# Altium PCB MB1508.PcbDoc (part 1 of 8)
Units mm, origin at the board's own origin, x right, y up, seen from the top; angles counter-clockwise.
Board outline 129 x 77 mm, 4 copper layers (Top Layer, GND, POWER, Bottom Layer), stack 1.582 mm thick; 399 components, 297 nets, 1407 pads, 1316 vias.
Unrouted connection lines stored in the file: 535.
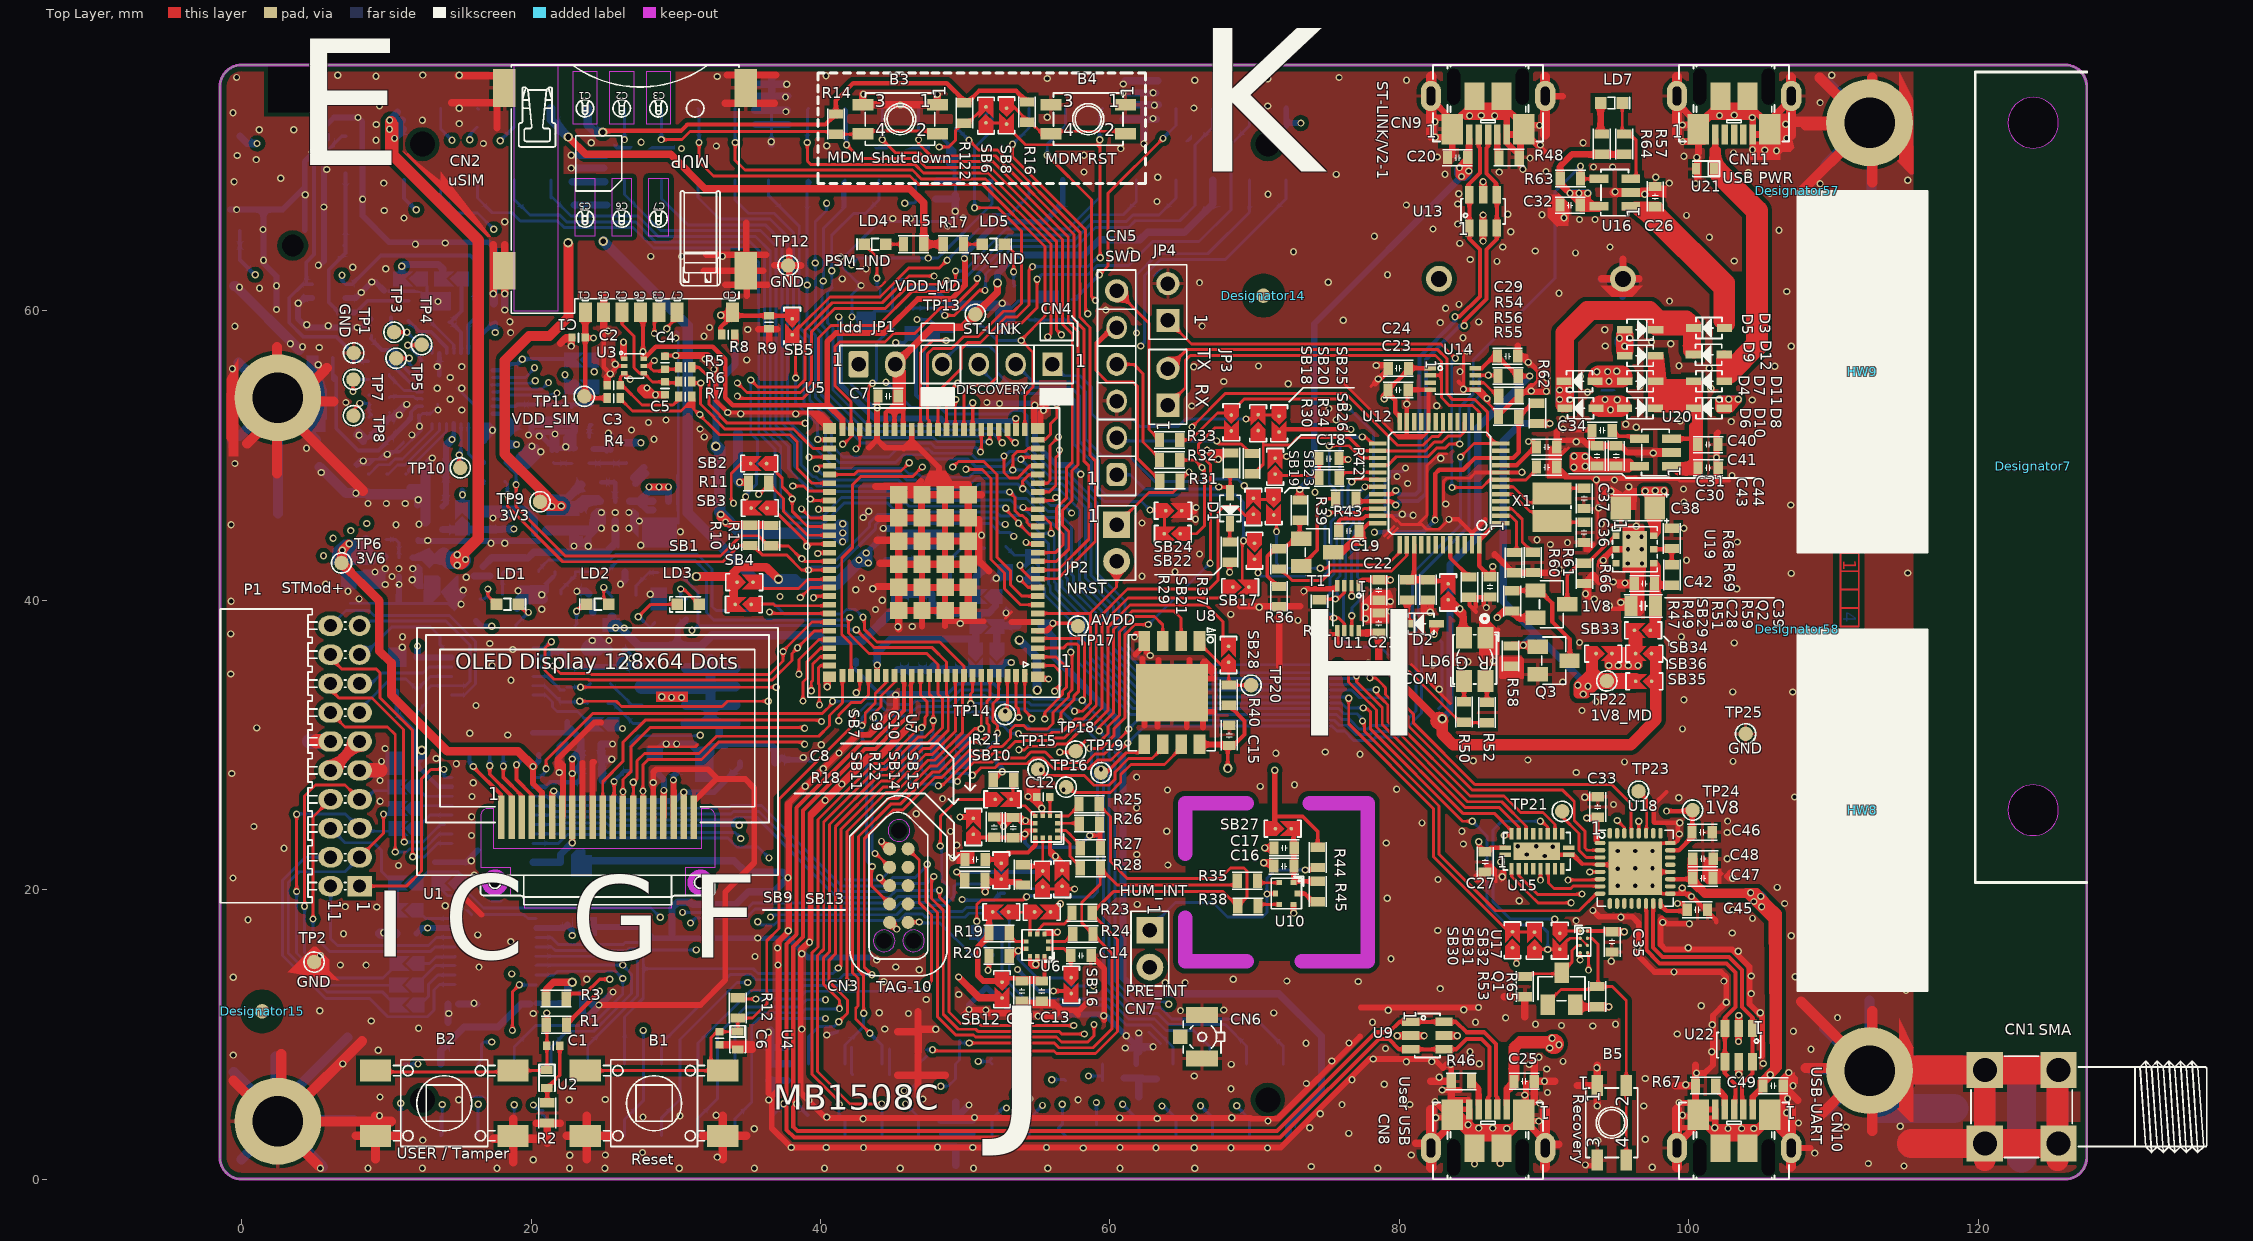
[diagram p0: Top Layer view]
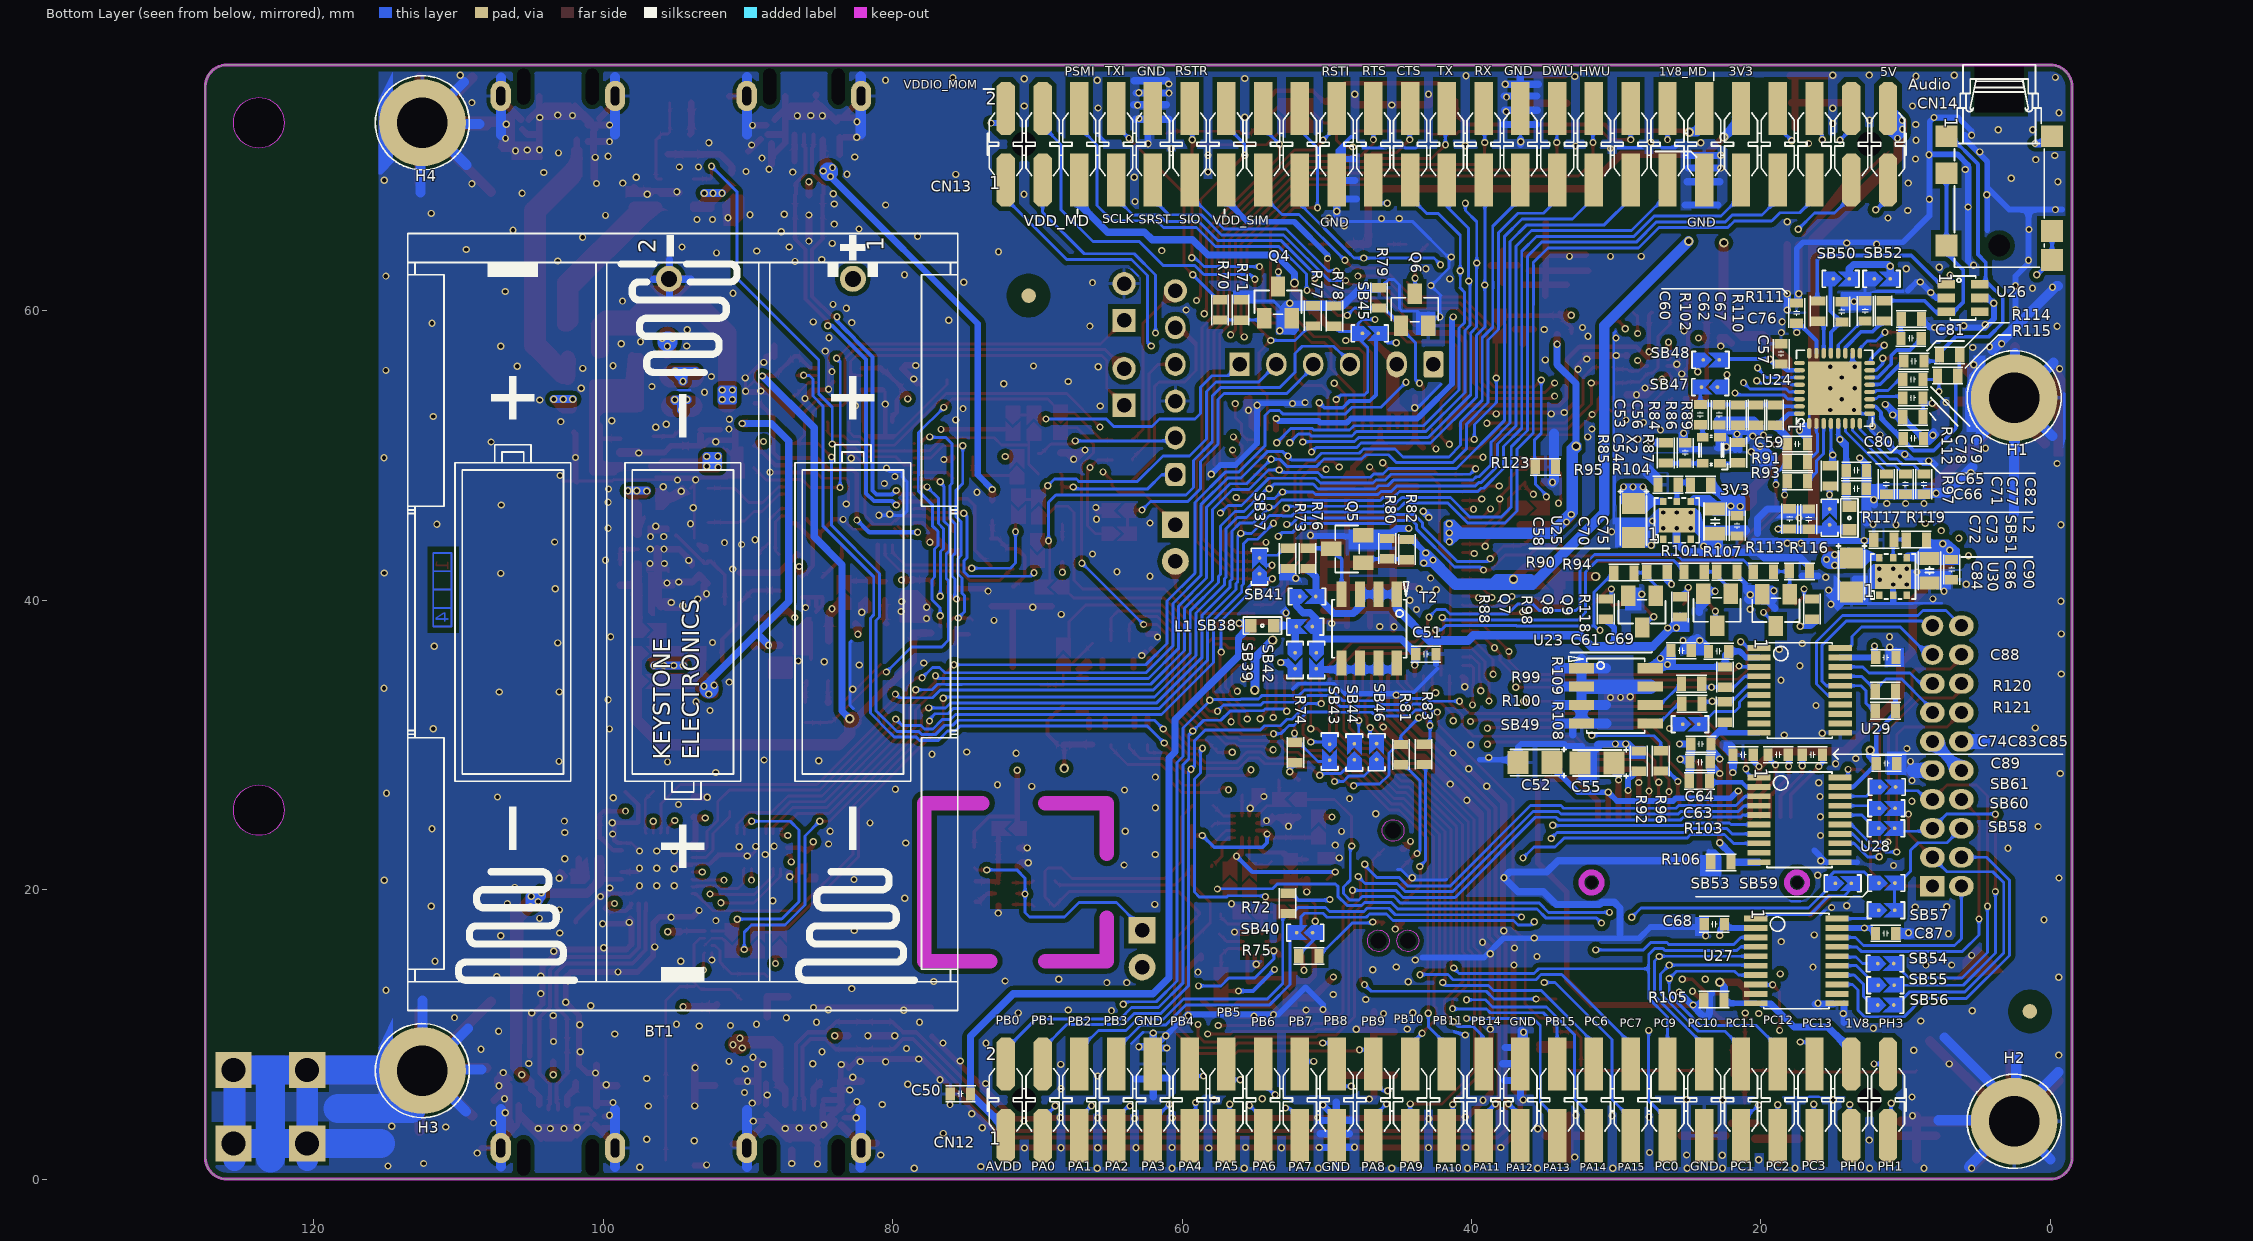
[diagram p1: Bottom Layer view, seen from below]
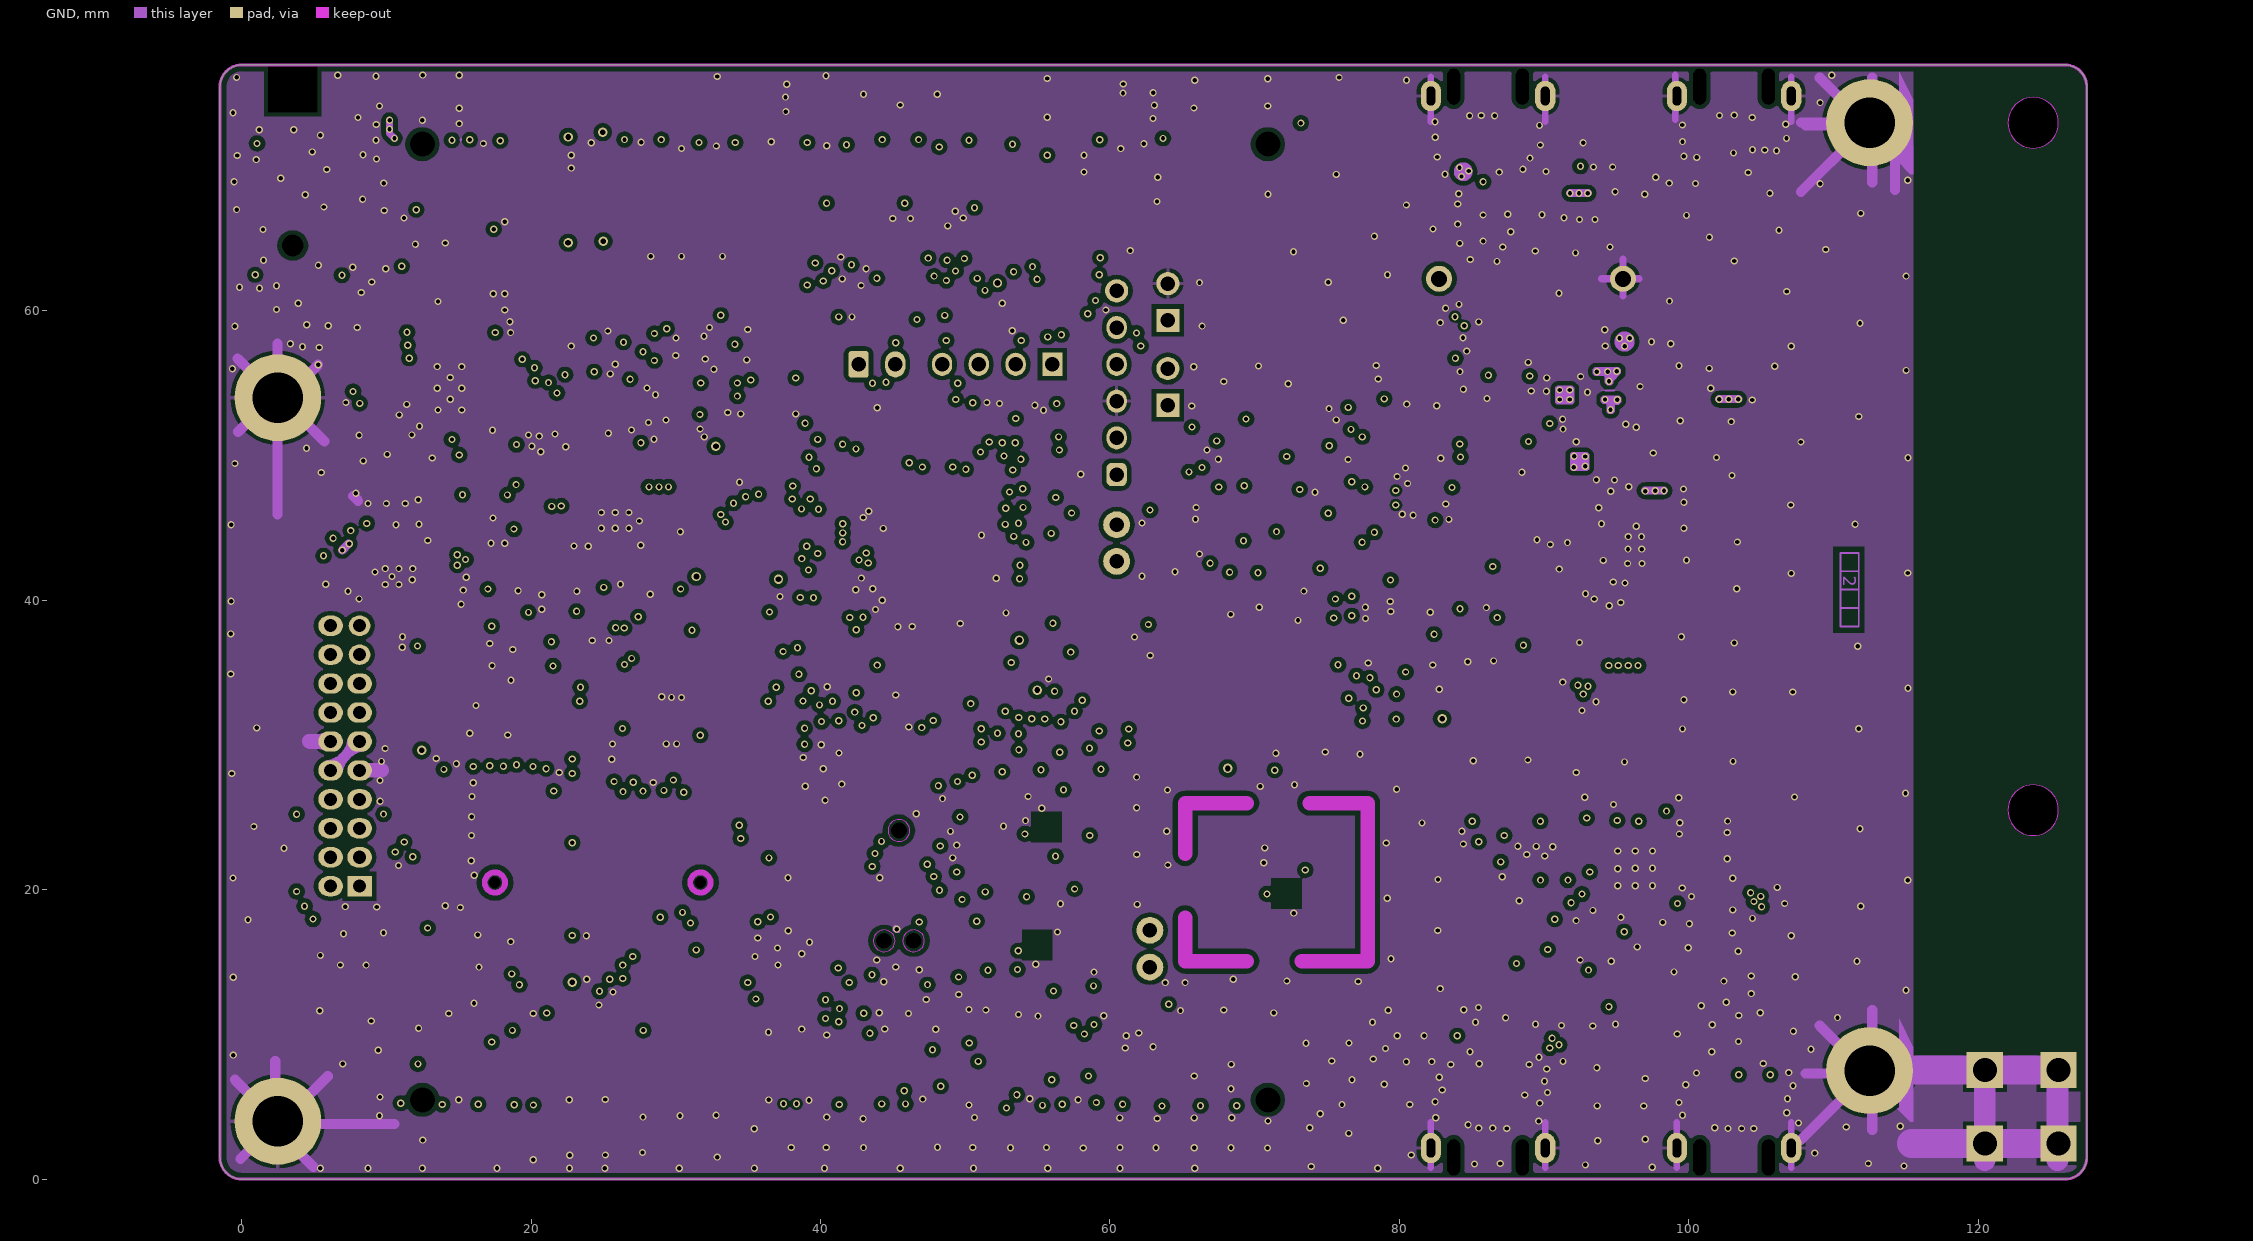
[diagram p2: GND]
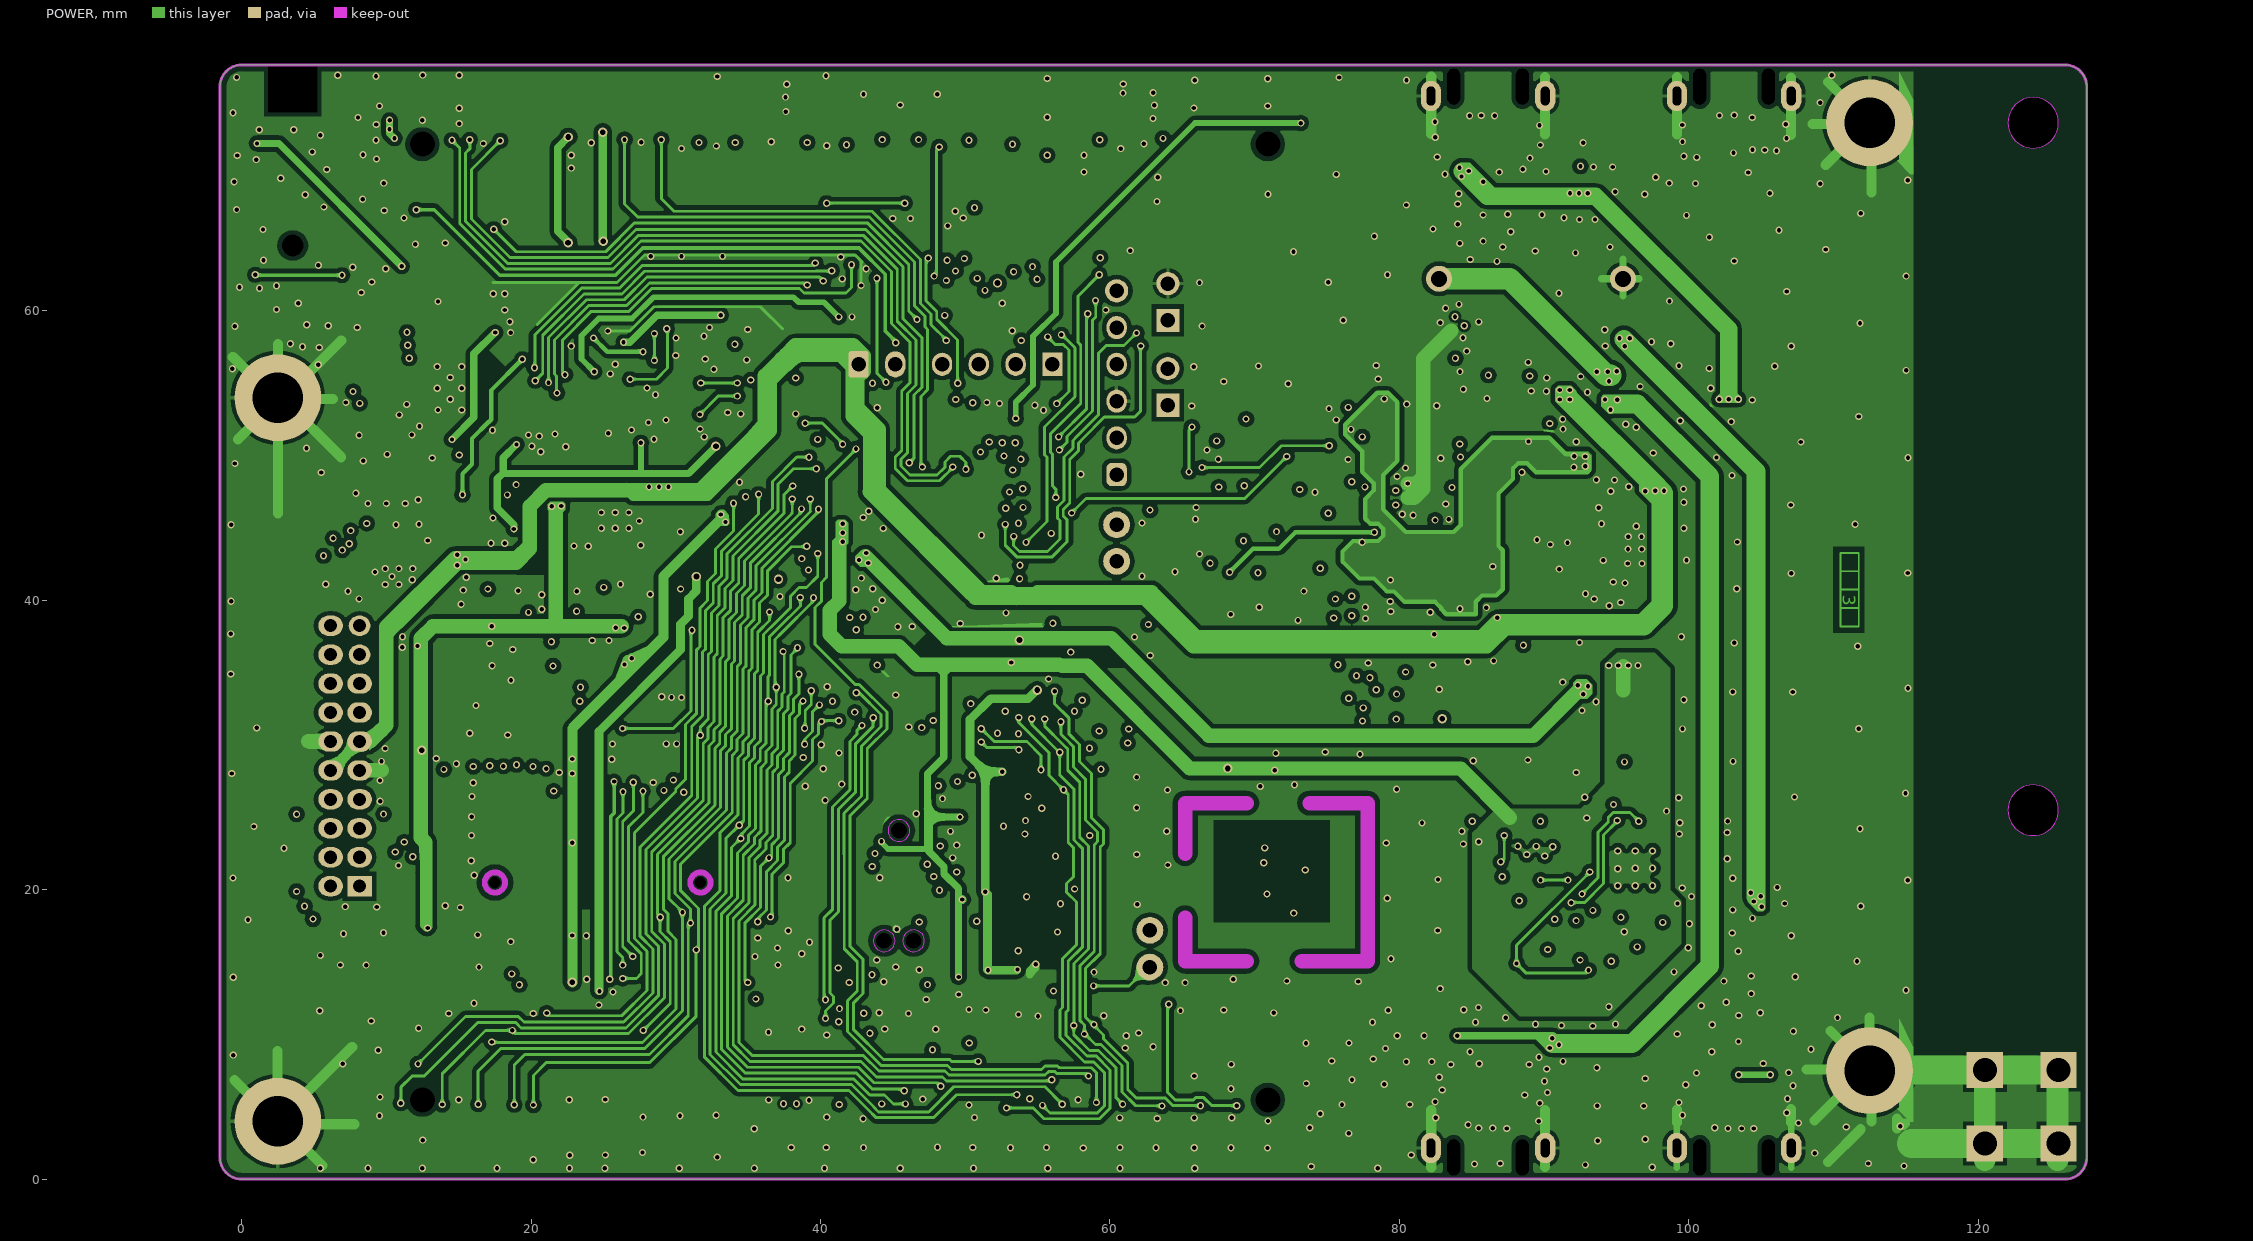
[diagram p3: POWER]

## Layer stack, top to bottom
Top Solder: solder mask 0.0102, Solder Resist, Dk 3.8
Top Layer: signal copper 0.0305
Dielectric 1: core 0.2159, FR-4, Dk 4.2
GND: signal copper 0.0305
Dielectric 2: prepreg 1.0287, Dk 4.4
POWER: signal copper 0.0305
Dielectric 3: core 0.2159, Dk 4.2
Bottom Layer: signal copper 0.0305
Bottom Solder: solder mask 0.0102, Solder Resist, Dk 3.8

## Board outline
-1.5,1.5 ccw(c0,1.5) 0,0 126,0 ccw(c126,1.5) 127.5,1.5 127.5,75.5 ccw(c126,75.5) 126,77 0,77 ccw(c0,75.5) -1.5,75.5
cut-out: 122.05,25.5 ccw(c123.8,25.5) 123.8,23.75 ccw(c123.8,25.5) 125.55,25.5 ccw(c123.8,25.5) 123.8,27.25 ccw(c123.8,25.5)
cut-out: 122.05,73 ccw(c123.8,73) 123.8,71.25 ccw(c123.8,73) 125.55,73 ccw(c123.8,73) 123.8,74.75 ccw(c123.8,73)

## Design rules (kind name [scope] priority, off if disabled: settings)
Clearance KEEP [IsKeepOut] p1: gap=0.35 ignorepadtopadclearanceinfootprint=FALSE
Clearance diff [InAnyDifferentialPair] p2: gap=0.178 ignorepadtopadclearanceinfootprint=FALSE
Clearance via [IsVia vs IsVia] p3: gap=0.4 ignorepadtopadclearanceinfootprint=FALSE
Clearance Polygon [InPolygon] p4: gap=0.3 ignorepadtopadclearanceinfootprint=FALSE
Clearance [All] p5: gap=0.2 ignorepadtopadclearanceinfootprint=FALSE
DiffPairsRouting [All] p1: maxlimit=0.254 minlimit=0.178 mostfreqgap=0.178 toplayer_minwidth=0.279 toplayer_maxwidth=0.279 toplayer_prefwidth=0.279 midlayer1_minwidth=0.279 midlayer1_maxwidth=0.279 midlayer1_prefwidth=0.279 midlayer2_minwidth=0.279 midlayer2_maxwidth=0.279 midlayer2_prefwidth=0.279 bottomlayer_minwidth=0.279 bottomlayer_maxwidth=0.279 bottomlayer_prefwidth=0.279 maxuncoupledlength=12.7
HoleSize [All] p1: absolutevalues=TRUE maxlimit=4 minlimit=0.025 maxpercent=80.000 minpercent=20.000
MinimumSolderMaskSliver [All] p1: minsoldermaskwidth=0
PolygonConnect one [InComponent('C20')] p1: thpad.connectstyle=Direct thpad.reliefconductorwidth=0.254 thpad.reliefentries=4 thpad.polygonreliefangle="90 Angle" thpad.airgapwidth=0.254 smdpad.connectstyle=Direct smdpad.reliefconductorwidth=0.254 smdpad.reliefentries=4 smdpad.polygonreliefangle="90 Angle" smdpad.airgapwidth=0.254 via.connectstyle=Relief via.reliefconductorwidth=0.254 via.reliefentries=4 via.polygonreliefangle="90 Angle" via.airgapwidth=0.254
PolygonConnect two [IsVia] p2: connectstyle=Direct reliefconductorwidth=0.254 reliefentries=4 polygonreliefangle="90 Angle" airgapwidth=0.254
PolygonConnect [All] p3: connectstyle=Relief reliefconductorwidth=0.254 reliefentries=4 polygonreliefangle="90 Angle" airgapwidth=0.254
RoutingCorners [All] p1: cornerstyle=45-Degree minsetback=5 maxsetback=5
RoutingVias [All] p1: holewidth=0.3 width=0.5 viastyle="Through Hole" minholewidth=0.254 minwidth=0.381 maxholewidth=5 maxwidth=8
SilkToSilkClearance [All] p1: silktosilkclearance=0
SilkToSolderMaskClearance [IsPad] p1: minsilkscreentomaskgap=0 clearancetoexposedcopper=TRUE
SolderMaskExpansion [All] p1: expansion=0.102
UnRoutedNet [All] p1 off: checkbadconnections=TRUE
Width [All] p1: maxlimit=3 minlimit=0.127 preferedwidth=0.2
23 further rules are at their usual default settings.

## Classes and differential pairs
component class U_Other: HW8 HW9 HW10 HW11 HW12 HW13 HW14 HW15 HW16 HW17
net class PH[0..3]: PH0 PH1 PH2 PH3
net class PC[0..13]: PC0 PC1 PC2 PC3 PC4 PC5 PC6 PC7 PC8 PC9 PC10 PC11 PC12 PC13
net class PB[0..15]: PB0 PB1 PB2 PB3 PB4 PB5 PB6 PB7 PB8 PB9 PB10 PB11 PB12 PB13 PB14 PB15
net class PA[0..15]: PA0 PA1 PA2 PA3 PA4 PA5 PA6 PA7 PA8 PA9 PA10 PA11 PA12 PA13 PA14 PA15
component class U_VoLTE: C53 C54 C56 C57 C59 C60 C62 C65 C66 C67 C71 C72 C73 C76 C77 C78 C79 C80 C81 C82 CN14 L2 R84 R85 R86 R87 R89 R91 R93 R97 R102 R110 R111 R112 R114 R115 SB47 SB48 SB50 SB51 SB52 SB69 SB81 TP3 TP4 TP5 TP7 TP8 TP10 U24 U26 X2
component class U_Uart2USB: B5 C27 C33 C35 C45 C46 C47 C48 C49 CN10 Q1 R53 R65 R67 SB30 SB31 SB32 SB83 SB84 SB85 TP21 TP23 U15 U17 U18 U22
component class U_ST_LINK_V2-1: C18 C19 C20 C21 C22 C23 C24 C26 C28 C29 C30 C31 C32 C34 C36 C37 C40 C41 C43 C44 C93 C94 CN4 CN5 CN9 D1 D2 D7 D8 D9 D10 D11 D13 D14 D15 D16 HW5 HW6 HW7 JP2 JP3 JP4 LD6 LD7 R29 R30 R31 R32 R33 R34 R36 R37 R39 R41 R42 R43 R47 R48 R49 R50 R51 R52 R54 R55 R56 R57 R60 R61 R62 R63 R64 SB17 SB18 SB19 SB20 SB21 SB22 SB23 SB24 SB25 SB26 SB29 SB35 SB36 SB71 SB72 SB73 SB74 SB75 SB76 SB77 SB78 SB79 SB80 SB87 SB88 T1 U11 U12 U13 U14 U16 U20 X1
component class U_SIM: C2 C3 C4 C5 CN2 R4 R5 R6 R7 R8 R9 SB5 U3
component class "U_Sensors & LCD": C8 C9 C10 C11 C12 C13 C14 C16 C17 C52 C55 C61 C63 C74 C83 C85 C95 C96 CN7 R3 R18 R19 R20 R21 R22 R23 R24 R25 R26 R27 R28 R35 R38 R44 R45 R72 R92 R96 R99 R100 R124 SB7 SB9 SB10 SB11 SB12 SB13 SB14 SB15 SB16 SB27 SB66 SB67 SB89 SB90 SB91 SB92 SB94 SB95 U1 U6 U7 U10 U23
component class U_Power: BT1 C38 C39 C42 C58 C70 C75 C84 C86 C90 CN11 D3 D4 D5 D6 D12 H1 H2 H3 H4 HW4 JP1 Q2 Q3 R58 R59 R66 R68 R69 R95 R104 R117 R119 SB33 SB34 TP1 TP2 TP6 TP9 TP12 TP13 TP24 TP25 U19 U21 U25 U30
component class U_Peripherals: C15 C25 CN3 CN8 LD1 LD2 LD3 Q7 Q8 Q9 Q10 R12 R40 R46 R75 R81 R83 R88 R90 R94 R98 R101 R107 R113 R116 R118 TP14 TP15 TP16 TP18 TP19 TP20 U8 U9
component class "U_Extension connectors": C64 C68 C69 C87 C88 C89 P1 R103 R105 R106 R108 R109 R120 R121 SB49 SB53 SB54 SB55 SB56 SB57 SB58 SB59 SB60 SB61 U27 U28 U29
component class U_1SE_Modem: B3 B4 C7 CN1 CN6 CN12 CN13 LD4 LD5 Q4 Q6 R10 R13 R14 R15 R16 R17 R70 R71 R73 R77 R78 R79 R122 R123 SB1 SB6 SB8 SB45 SB93 TP11 TP22 U5
component class U_1SE_MCU: B1 B2 C1 C6 C50 C51 C91 C92 HW1 HW2 L1 Q5 R1 R2 R11 R74 R76 R80 R82 SB2 SB3 SB4 SB28 SB37 SB38 SB39 SB40 SB41 SB42 SB43 SB44 SB46 T2 TP17 U2 U4
differential pair STL_USB_D: +STL_USB_D_P -STL_USB_D_N
differential pair User_USB: +PA12 -PA11
differential pair USB_C: +NetCN10_2 -NetCN10_3

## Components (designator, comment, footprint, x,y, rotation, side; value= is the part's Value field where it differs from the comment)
B1 "SW-PUSH-CMS" SWI_WEALTHMETAL_TD-0341_4P_BLACK 28.5,5.25 r270 top locked value=SWITCH
B2 "SW-PUSH-CMS" SWI_WEALTHMETAL_TD-0341_4P_BLUE 14,5.25 r270 top locked value=SWITCH
B3 "SW-PUSH-CMS_EVQP2_BLACK" SWI_PANASONIC_EVQP2F02K 45.5,73.25 r0 top locked value=EVQP2F02K
B4 "SW-PUSH-CMS_EVQP2_BLACK" SWI_PANASONIC_EVQP2F02K 58.5,73.25 r0 top value=EVQP2F02K
B5 "SW-PUSH-CMS_EVQP2_BLACK" SWI_PANASONIC_EVQP2F02K 94.68,3.9 r90 top locked value=EVQP2F02K
BT1 "BATTERY HOLDER 3 x AAA" BAT_KEYSTONE_PC-MOUNT-2479_HOLDER_AAA_X3 94.5,38.499 r90 bottom locked value=2479
C1 "Capacitor" C0402 21.538,9.22 r180 top value=100nF
C2 "Capacitor" C0402 23.281,58.151 r180 top value=100nF
C3 "Capacitor" C0402 25.718,54.862 r0 top value=33pF
C4 "Capacitor" C0402 29.255,56.421 r270 top value=33pF
C5 "Capacitor" C0402 29.255,54.644 r90 top value=33pF
C6 "Capacitor" C0402 33.021,9.74 r90 top value=100nF
C7 "Capacitor" C0603 44.677,54.11 r0 top
C8 "Capacitor" C0603 50.687,22.094 r0 top value=100nF
C9 "Capacitor" C0603 52.008,24.331 r270 top value=10uF
C10 "Capacitor" C0603 53.313,24.3 r270 top value=100nF
C11 "Capacitor" C0603 53.918,12.998 r270 top value=4.7uF
C12 "Capacitor" C0402 55.387,26.409 r180 top value=220nF
C13 "Capacitor" C0603 55.292,12.998 r90 top value=100nF
C14 "Capacitor" C0603 58.002,15.451 r180 top value=100nF
C15 "Capacitor" C0603 68.25,30.676 r270 top value=100nF
C16 "Capacitor" C0603 72.029,21.631 r0 top value=100nF
C17 "Capacitor" C0603 72.04,22.891 r180 top value=2.2uF
C18 "[N/A]" C0603 75.135,49.79 r0 top value=20pF
C19 "Capacitor" C0603 76.515,44.793 r0 top value=100nF
C20 "Capacitor" C0603 84.03,70.59 r0 top value=100nF
C21 "Capacitor" C0603 78.585,38.424 r90 top value=100nF
C22 "Capacitor" C0603 78.585,40.714 r90 top value=100nF
C23 "Capacitor" C0603 79.924,54.537 r180 top value=100nF
C24 "Capacitor" C0603 79.932,56.028 r0 top value=100nF
C25 "Capacitor" C0603 88.63,6.76 r180 top value=100nF
C26 "Capacitor" C0603 97.678,67.895 r270 top value=100nF
C27 "Capacitor" C0603 85.929,21.924 r270 top value=470nF
C28 "Capacitor" C0603 86.267,40.93 r90 top value=100nF
C29 "Capacitor" C0603 87.485,56.871 r0 top value=100nF
C30 "Capacitor" C0603 90.184,49.201 r0 top value=100nF
C31 "Capacitor" C0603 90.184,50.59 r180 top value=100nF
C32 "Capacitor" C0603 91.794,67.306 r180 top value=1uF
C33 "Capacitor" C0603 93.709,25.718 r270 top value=100nF
C34 "Capacitor" C0603 94.02,51.746 r0 top value=10nF
C35 "Capacitor" C0603 94.701,16.4 r270 top value=470nF
C36 "Capacitor" C0603 92.763,44.691 r90 top value=10pF
C37 "Capacitor" C0603 92.768,47.042 r90 top value=10pF
C38 "Cap_POL_TANA" CPOL_TAJ-A_1206_H180 96.475,46.391 r180 top value="4.7uF 16V"
C39 "Capacitor" C0805 96.864,39.613 r180 top value=10uF
C40 "Capacitor" C0603 101.326,50.763 r180 top value=1uF
C41 "Capacitor" C0603 101.335,49.163 r180 top value=100nF
C42 "Capacitor" C0603 96.933,41.162 r0 top value=100nF
C43 "Capacitor" C0603 93.664,49.977 r270 top value=100nF
C44 "Capacitor" C0603 94.985,49.977 r270 top value=1uF
C45 "Capacitor" C0603 100.59,18.618 r0 top value=1uF
C46 "Capacitor" C0603 100.929,23.977 r0 top value=4.7uF
C47 "Capacitor" C0603 100.982,20.804 r0 top value=1uF
C48 "Capacitor" C0603 100.983,22.138 r180 top value=100nF
C49 "Capacitor" C0603 105.83,6.449 r180 top value=100nF
C50 "Capacitor" C0603 75.314,5.894 r0 bottom value=1uF
C51 "Capacitor" C0603 43.15,36.274 r180 bottom value=1uF
C52 "Cap_POL_TANA" CPOL_TAJ-A_1206_H180 35.605,28.784 r0 bottom value="4.7uF 16V"
C53 "Capacitor" C0603 24.184,52.83 r90 bottom
C54 "Capacitor" C0603 25.23,50.192 r270 bottom
C55 "Cap_POL_TANA" CPOL_TAJ-A_1206_H180 31.312,28.753 r0 bottom value="4.7uF 16V"
C56 "Capacitor" C0603 22.884,52.815 r90 bottom value=10pF
C57 "Capacitor" C0603 18.609,57.032 r90 bottom value=1uF
C58 "Cap_POL_TANA" CPOL_TAJ-A_1206_H180 28.812,45.513 r270 bottom value="4.7uF 16V"
C59 "Capacitor" C0603 17.48,50.8 r180 bottom
C60 "Capacitor" C0603 17.531,59.853 r90 bottom value=1uF
C61 "Capacitor" C0603 25.507,36.525 r180 bottom value=100nF
C62 "Capacitor" C0603 14.407,59.941 r90 bottom value=1uF
C63 "Capacitor" C0603 24.205,28.82 r0 bottom value=1uF
C64 "Capacitor" C0603 24.154,30.065 r0 bottom value=100nF
C65 "Capacitor" C0603 13.401,48.979 r180 bottom
C66 "Capacitor" C0603 13.413,47.709 r0 bottom value=100nF
C67 "Capacitor" C0603 12.797,59.996 r90 bottom value=1uF
C68 "Capacitor" C0603 23.222,17.616 r0 bottom value=100nF
C69 "Capacitor" C0603 22.93,36.474 r0 bottom value=100nF
C70 "Capacitor" C0805 23.167,45.451 r270 bottom value=10uF
C71 "Capacitor" C0603 11.33,48.03 r90 bottom value=2.2uF
C72 "Capacitor" C0603 18.017,45.626 r270 bottom value=100nF
C73 "Capacitor" C0603 16.695,45.611 r90 bottom value=1uF
C74 "Capacitor" C0603 21.226,29.328 r180 bottom value=1uF
C75 "Capacitor" C0603 21.649,45.151 r90 bottom value=100nF
C76 "Capacitor" C0603 9.626,58.105 r180 bottom value=1uF
C77 "Capacitor" C0603 10.016,48.03 r90 bottom value=1uF
C78 "Capacitor" C0603 9.496,53.986 r0 bottom value=1uF
C79 "Capacitor" C0603 9.496,55.26 r0 bottom value=1uF
C80 "Capacitor" C0603 9.466,51.191 r0 bottom value=1uF
C81 "Capacitor" C0603 9.434,56.53 r0 bottom value=1uF
C82 "Capacitor" C0603 8.734,48.03 r90 bottom value=1uF
C83 "Capacitor" C0603 18.81,29.328 r0 bottom value=1uF
C84 "Cap_POL_TANA" CPOL_TAJ-A_1206_H180 13.742,41.753 r270 bottom value="4.7uF 16V"
C85 "Capacitor" C0603 16.44,29.328 r180 bottom value=1uF
C86 "Capacitor" C0805 8.351,42.047 r270 bottom value=10uF
C87 "Capacitor" C0603 11.374,16.981 r0 bottom value=100nF
C88 "Capacitor" C0603 11.373,36.042 r0 bottom value=100nF
C89 "Capacitor" C0603 11.322,28.727 r0 bottom value=100nF
C90 "Capacitor" C0603 6.822,42.124 r90 bottom value=100nF
CN1 "SLC-100180065" CON_ROHO_SMA_RFSMARA-7053 123,5 r180 top locked
CN2 "MUP-C792" CON_MICRO-SIMCARD_MUP_MUP-C792 26.5,77 r180 top locked
CN3 "Tag-10-C" CON_TAG-C_TC2050-IDC-NL 45.416,20.284 r270 top locked value=TC2050-IDC-NL
CN4 "Header 4x1" CON_988-JIUBABA_PHFS25-11-04-G0B115-T-1 52.214,56.308 r0 top locked
CN5 "Header 6x1" CON_988-JIUBABA_PHFS25-11-06-G0B115-T-1 60.464,55.038 r270 top locked value="Header 1x6"
CN6 "U.FL-R-SMT-1" CON_HRS_U.FL-R-SMT-1 66.373,9.831 r270 top
CN7 "Header 2x1" CON_SAMTEC_TSW-102-08-G-S 62.764,15.927 r270 top
CN8 "USB_uB_105164-0001" CON_USBMICROB_MOLEX_105164-0001_H2P45 86.13,0.7 r90 top locked
CN9 "USB_uB_105164-0001" CON_USBMICROB_MOLEX_105164-0001_H2P45 86.13,76.3 r270 top locked
CN10 "USB_uB_105164-0001" CON_USBMICROB_MOLEX_105164-0001_H2P45 103.13,0.7 r90 top locked
CN11 "USB_uB_105164-0001" CON_USBMICROB_MOLEX_105164-0001_H2P45 103.13,76.3 r270 top locked
CN12 "Header 25x2" CON_SAMTEC_TSM-125-01-F-DV-A 41.7,5.48 r180 bottom locked
CN13 "Header 25x2" CON_SAMTEC_TSM-125-01-F-DV-A 41.7,71.52 r180 bottom locked
CN14 "PJ-31060" CON_PHONE-JACK-3P5_TAIYI_PJ31060 3.529,75.019 r270 bottom locked
D1 "BAT60JFILM" DIO_SOD323 68.308,46.355 r270 top
D2 "BAT60JFILM" DIO_SOD323 81.502,38.382 r180 top
D3 "BAT60JFILM" DIO_SOD323 101.401,58.815 r180 top
D4 "BAT60JFILM" DIO_SOD323 92.451,55.145 r180 top
D5 "BAT60JFILM" DIO_SOD323 96.639,58.695 r0 top
D6 "BAT60JFILM" DIO_SOD323 92.521,53.277 r180 top
D7 "BAT60JFILM" DIO_SOD323 96.639,55.145 r0 top
D8 "BAT60JFILM" DIO_SOD323 101.393,53.277 r180 top
D9 "BAT60JFILM" DIO_SOD323 96.639,56.895 r0 top
D10 "BAT60JFILM" DIO_SOD323 96.634,53.277 r0 top
D11 "BAT60JFILM" DIO_SOD323 101.393,55.145 r180 top
D12 "BAT60JFILM" DIO_SOD323 101.371,56.978 r180 top
Designator7 "Comment" 预留天线 129.8,38.5 r0 top locked
Designator14 "Comment" MARK 70.605,61.055 r0 top
Designator15 "Comment" MARK 1.414,11.596 r0 top
Designator57 "Comment" Label 107.5,68.3 r270 top
Designator58 "Comment" Label 107.5,38 r270 top
H1 "POSITION HOLE" PTH_M1261-3005-N_3P5X6_M3_H14 2.5,54 r180 bottom locked
H2 "POSITION HOLE" PTH_M1261-3005-N_3P5X6_M3_H14 2.5,4 r180 bottom
H3 "POSITION HOLE" PTH_M1261-3005-N_3P5X6_M3_H14 112.5,7.5 r180 bottom
H4 "POSITION HOLE" PTH_M1261-3005-N_3P5X6_M3_H14 112.5,73 r180 bottom locked
HW8 "STICKER_BOARD_REF" STICKER_25X9 112,25.5 r90 top value="MBxxxxy-zz syywwxxxxx"
HW9 "STICKER_BOARD_CPN" STICKER_25X9 112,55.8 r90 top value="Board CPN"
JP1 "Jumper_Header 2x1 Fitted" CON_SAMTEC_TSW-102-07-G-S#1 43.904,56.308 r0 top locked value="Shunt Fitted"
JP2 "Jumper_Header 2x1 Fitted" CON_SAMTEC_TSW-102-07-G-S#2 60.464,43.959 r270 top value="Shunt Fitted"
JP3 "Jumper_Header 2x1" CON_SAMTEC_TSW-102-07-G-S#3 64.004,54.748 r90 top value="Shunt not fitted"
JP4 "Jumper_Header 2x1" CON_SAMTEC_TSW-102-07-G-S#3 64.004,60.618 r90 top value="Shunt not fitted"
L1 "BEAD" L0603 54.457,38.251 r180 bottom value=600R@100MHz
L2 "BEAD" L0603_H0P8 13.884,45.691 r270 bottom value="1000R @ 100MHz"
LD1 "LED_green" LED_0603_GREEN_H0P8 18.359,39.725 r0 top value=GREEN
LD2 "LED_red" LED_0603_RED_H0P4 24.609,39.725 r180 top value=RED
LD3 "LED_blue" LED_0603_OSRAM_LB-Q39G-L2OO-35-1_BLUE_1A2K_H0P4 30.859,39.725 r180 top value=BLUE
LD4 "LED_green" LED_0603_GREEN_H0P8 43.773,64.608 r180 top value=GREEN
LD5 "LED_green" LED_0603_GREEN_H0P8 51.94,64.608 r0 top value=GREEN
LD6 "LD_BICOLOR_CMS" LED_BI-GR_HSMF-A201-A00J1 85.208,35.92 r180 top
LD7 "LED_red" LED_0603_RED 94.654,74.368 r0 top value=RED
P1 "Socket 10X2 STMod+" CON_SAMTEC_SQT-110-01-F-D-RA__STMOD+ 7.15,29.246 r270 top locked
Q1 "MOSFET_FDN304P" MOS_SOT23 91.208,13.162 r0 top value=FDN304P
Q2 "MOSFET_FDN304P" MOS_SOT23 90.506,39.73 r270 top value=FDN304P
Q3 "BSN20" MOS_SOT23 90.666,35.833 r270 top value=FDN327N
Q4 "9013-SOT23" NPN_SOT23 53.372,60.587 r180 bottom value="NPN SOT23"
Q5 "9013-SOT23" NPN_SOT23 48.589,43.552 r90 bottom value="NPN SOT23"
Q6 "BSN20" MOS_SOT23 43.923,60.078 r180 bottom value=FDN327N
Q7 "9013-SOT23" NPN_SOT23 28.212,39.221 r0 bottom value="NPN SOT23"
Q8 "9013-SOT23" NPN_SOT23 23.031,39.348 r0 bottom value="NPN SOT23"
Q9 "9013-SOT23" NPN_SOT23 18.967,39.323 r0 bottom value="NPN SOT23"
R1 "Resistor" R0603 21.741,10.668 r0 top value=10K
R2 "Resistor" R0603 21.122,4.584 r90 top value=100R
R3 "Resistor" R0603 21.725,12.476 r0 top value=10K
R4 "Resistor" R0402 25.707,53.976 r180 top value=15K
R5 "Resistor" R0402 30.659,56.105 r180 top value=18R
R6 "Resistor" R0402 30.659,55.118 r180 top value=18R
R7 "Resistor" R0402 30.659,54.073 r180 top value=18R
R8 "Resistor" R0402 33.632,58.358 r0 top value=15K
R9 "Resistor" R0402 36.443,59.216 r270 top value=15K
R10 "Resistor" R0603 35.147,44.489 r90 top value=10K
R11 "Resistor" R0603 35.722,48.13 r0 top value=10K
R12 "Resistor" R0603 34.278,11.829 r270 top value=22R
R13 "Resistor" R0603 36.595,44.463 r90 top value=10K
R14 "Resistor" R0603 41.066,72.908 r270 top value=100K
R15 "Resistor" R0603 46.429,64.608 r0 top value=510R
R16 "Resistor" R0603 54.278,73.743 r90 top value=100K
R17 "Resistor" R0603 49.183,64.608 r180 top value=510R
R18 "Resistor" R0603 50.672,20.701 r180 top value=10K
R19 "Resistor" R0603 52.345,16.981 r0 top value=0R
R20 "Resistor" R0603 52.346,15.414 r0 top value=10K
R21 "Resistor" R0603 52.647,27.59 r0 top value=10K
R22 "Resistor" R0603 53.975,21.035 r90 top value=10K
R23 "Resistor" R0603 58.078,18.408 r180 top value=0R
R24 "Resistor" R0603 58.129,16.939 r180 top value=0R
R25 "Resistor" R0603 58.569,25.913 r180 top value=0R
R26 "Resistor" R0603 58.573,24.576 r0 top value=0R
R27 "Resistor" R0603 58.649,22.863 r0 top value=0R
R28 "Resistor" R0603 58.655,21.48 r180 top value=0R
R29 "[N/A]" R0603 68.272,43.337 r270 top value=22R
R30 "Resistor" R0603 68.393,49.479 r90 top value=10K
R31 "Resistor" R0603 64.143,48.271 r0 top value=22R
R32 "Resistor" R0603 64.126,49.691 r0 top value=22R
R33 "Resistor" R0603 64.122,51.079 r0 top value=22R
R34 "Resistor" R0603 69.793,49.443 r270 top value=22R
R35 "Resistor" R0603 69.492,20.626 r0 top value=0R
R36 "Resistor" R0603 71.689,40.253 r90 top value=36K
R37 "Resistor" R0603 71.689,42.858 r270 top value=100R
R38 "Resistor" R0603 69.54,18.848 r0 top value=0R
R39 "Resistor" R0603 73.111,46.228 r90 top value=10K
R40 "Resistor" R0603 68.212,33.453 r90 top value=10K
R41 "[N/A]" R0603 74.483,39.333 r270 top value=100R
R42 "Resistor" R0603 75.155,48.464 r180 top value=100R
R43 "Resistor" R0603 76.311,47.015 r180 top value=1K5
R44 "Resistor" R0603 74.358,22.23 r90 top value=10K
R45 "Resistor" R0603 74.365,19.879 r270 top value=0R
R46 "Resistor" R0603 84.28,6.76 r180 top value=100K
R47 "Resistor" R0603 80.548,40.73 r90 top value=2K7
R48 "Resistor" R0603 87.58,70.59 r0 top value=100K
R49 "Resistor" R0603 81.973,40.73 r270 top value=4K7
R50 "Resistor" R0603 84.469,32.283 r90 top value=330R
R51 "Resistor" R0603 84.845,40.904 r90 top value=100K
R52 "Resistor" R0603 86.049,32.248 r90 top value=330R
R53 "Resistor" R0603 88.667,13.31 r270 top value=10K
R54 "Resistor" R0603 87.511,55.499 r0 top value=100K
R55 "Resistor" R0603 87.551,52.673 r0 top value=4K7
R56 "Resistor" R0603 87.561,54.153 r180 top value=10K
R57 "Resistor" R0603 95.544,71.523 r270 top value=47K
R58 "Resistor" R0603 87.693,36.145 r90 top value=100K
R59 "Resistor" R0603 87.806,39.966 r270 top value=100K
R60 "Resistor" R0603 87.894,42.598 r90 top value=10K
R61 "[N/A]" R0603 89.215,42.621 r90 top value=10K
R62 "Resistor" R0603 89.539,52.925 r90 top value=4K7
R63 "Resistor" R0603 91.817,69.149 r180 top value=47K
R64 "Resistor" R0603 93.984,71.523 r270 top value=1K
R65 "Resistor" R0603 93.68,12.61 r90 top value=10K
R66 "Resistor" R0603 92.794,41.863 r90 top value=100K
R67 "Resistor" R0603 101.162,6.462 r0 top value=100K
R68 "Resistor" R0603 98.822,44.275 r270 top value=43K
R69 "Resistor" R0603 98.835,41.75 r270 top value=20K5
R70 "Resistor" R0603 57.37,60.075 r90 bottom value=47K
R71 "Resistor" R0603 55.955,60.062 r270 bottom value=100K
R72 "Resistor" R0603 52.709,19.064 r90 bottom value=10K
R73 "Resistor" R0603 52.703,42.892 r270 bottom value=100K
R74 "Resistor" R0603 52.165,29.484 r270 bottom value=10K
R75 "Resistor" R0603 51.233,15.414 r0 bottom value=22R
R76 "Resistor" R0603 51.325,42.892 r270 bottom value=1K
R77 "Resistor" R0603 50.972,59.662 r270 bottom value=100K
R78 "Resistor" R0603 49.475,59.64 r90 bottom value=0R
R79 "Resistor" R0603 46.38,60.897 r270 bottom value=100K
R80 "Resistor" R0603 45.82,43.577 r270 bottom value=10K
R81 "Resistor" R0603 44.884,29.334 r270 bottom value=22R
R82 "Resistor" R0603 44.462,43.499 r90 bottom value=10K
R83 "Resistor" R0603 43.309,29.359 r270 bottom value=22R
R84 "Resistor" R0603 21.584,52.79 r270 bottom value=10K
R85 "Resistor" R0603 26.579,50.192 r90 bottom
R86 "Resistor" R0603 20.314,52.803 r90 bottom value=47K
R87 "Resistor" R0603 21.555,50.211 r270 bottom value=0R
R88 "Resistor" R0603 30.727,39.399 r270 bottom value=510R
R89 "Resistor" R0603 19.019,52.805 r270 bottom value=47K
R90 "Resistor" R0603 29.471,41.914 r0 bottom value=47K
R91 "Resistor" R0603 17.48,49.527 r180 bottom value=0R
R92 "Resistor" R0603 28.442,28.894 r270 bottom value=620K
R93 "Resistor" R0603 17.48,48.231 r180 bottom value=0R
R94 "Resistor" R0603 27.182,41.964 r0 bottom value=100K
R95 "Resistor" R0603 26.418,47.988 r180 bottom value=11K8
R96 "Resistor" R0603 26.918,28.905 r90 bottom value=0R
R97 "Resistor" R0603 15.26,48.599 r90 bottom value=10K
R98 "Resistor" R0603 25.596,39.551 r270 bottom value=510R
R99 "Resistor" R0603 24.793,34.239 r180 bottom value=0R
R100 "Resistor" R0603 24.768,32.851 r180 bottom value=0R
R101 "Resistor" R0603 24.62,41.978 r0 bottom value=47K
R102 "Resistor" R0603 16.032,59.98 r90 bottom
R103 "Resistor" R0603 24.25,27.525 r0 bottom value=10K
R104 "Resistor" R0603 24.171,47.993 r180 bottom value=20K5
R105 "Resistor" R0603 23.247,12.409 r0 bottom value=10K
R106 "Resistor" R0603 22.761,21.886 r0 bottom value=10K
R107 "Resistor" R0603 22.35,41.978 r0 bottom value=100K
R108 "Resistor" R0603 22.498,32.283 r90 bottom value=4K7
R109 "Resistor" R0603 22.473,34.696 r270 bottom value=4K7
R110 "Resistor" R0603 11.527,60.01 r90 bottom value=0R
R111 "Resistor" R0603 9.61,59.44 r0 bottom value=0R
R112 "Resistor" R0603 9.507,52.657 r180 bottom value=2K15
R113 "Resistor" R0603 19.83,41.978 r0 bottom value=47K
R114 "Resistor" R0603 6.961,56.93 r180 bottom value=2K15
R115 "Resistor" R0603 7.096,55.53 r180 bottom value=2K15
R116 "Resistor" R0603 17.34,41.995 r0 bottom value=100K
R117 "Resistor" R0603 11.506,44.183 r180 bottom value=10K2
R118 "Resistor" R0603 16.466,39.396 r270 bottom value=510R
R119 "Resistor" R0603 9.265,44.199 r180 bottom value=20K5
R120 "Resistor" R0603 11.407,33.761 r0 bottom value=4K7
R121 "Resistor" R0603 11.398,32.373 r0 bottom value=4K7
R122 "Resistor" R0603 49.945,73.675 r90 top value=10K
R123 "Resistor" R0603 34.888,49.224 r180 bottom value=0R
SB1 "SB_ON" SOLDER-BRIDGE_R0603-0R 34.735,41.252 r0 top
SB2 "SB_ON" SOLDER-BRIDGE_R0603-0R 35.771,49.451 r180 top
SB3 "SB_ON" SOLDER-BRIDGE_R0603-0R 35.808,46.377 r180 top
SB4 "SB_ON" SOLDER-BRIDGE_R0603-0R 34.707,39.716 r180 top
SB5 "SB_ON" SOLDER-BRIDGE_R0603-0R 38.047,58.952 r270 top
SB6 "SB_OFF" SOLDER-BRIDGE_R0603-0R 51.434,73.496 r90 top
SB7 "SB_ON" SOLDER-BRIDGE_R0603-0R 50.563,24.332 r90 top
SB8 "SB_ON" SOLDER-BRIDGE_R0603-0R 52.856,73.512 r270 top
SB9 "SB_ON" SOLDER-BRIDGE_R0603-0R 52.498,18.466 r180 top
SB10 "SB_ON" SOLDER-BRIDGE_R0603-0R 52.574,26.244 r0 top
SB11 "SB_ON" SOLDER-BRIDGE_R0603-0R 52.49,21.337 r270 top
SB12 "SB_ON" SOLDER-BRIDGE_R0603-0R 52.546,13.118 r270 top
SB13 "SB_OFF" SOLDER-BRIDGE_R0603-0R 55.293,18.466 r0 top
SB14 "SB_ON" SOLDER-BRIDGE_R0603-0R 55.352,20.695 r90 top
SB15 "SB_ON" SOLDER-BRIDGE_R0603-0R 56.693,20.735 r90 top
SB16 "SB_ON" SOLDER-BRIDGE_R0603-0R 57.319,13.432 r270 top
SB17 "SB_ON" SOLDER-BRIDGE_R0603-0R 68.998,40.916 r0 top
SB18 "SB_ON" SOLDER-BRIDGE_R0603-0R 68.393,52.303 r270 top
SB19 "SB_ON" SOLDER-BRIDGE_R0603-0R 69.916,46.447 r90 top
SB20 "SB_ON" SOLDER-BRIDGE_R0603-0R 70.245,52.232 r90 top
SB21 "SB_OFF" SOLDER-BRIDGE_R0603-0R 69.992,43.437 r270 top
SB22 "SB_ON" SOLDER-BRIDGE_R0603-0R 64.349,44.601 r180 top
SB23 "SB_OFF" SOLDER-BRIDGE_R0603-0R 71.316,46.497 r270 top
SB24 "SB_OFF" SOLDER-BRIDGE_R0603-0R 64.361,46.195 r0 top
SB25 "SB_OFF" SOLDER-BRIDGE_R0603-0R 71.689,52.23 r270 top
SB26 "SB_OFF" SOLDER-BRIDGE_R0603-0R 71.416,49.223 r90 top
SB27 "SB_ON" SOLDER-BRIDGE_R0603-0R 71.937,24.222 r0 top
SB28 "SB_OFF" SOLDER-BRIDGE_R0603-0R 68.198,36.22 r90 top
SB29 "SB_OFF" SOLDER-BRIDGE_R0603-0R 83.371,40.538 r90 top
SB30 "SB_ON" SOLDER-BRIDGE_R0603-0R 87.818,16.5 r90 top
SB31 "SB_OFF" SOLDER-BRIDGE_R0603-0R 89.342,16.472 r90 top
SB32 "SB_OFF" SOLDER-BRIDGE_R0603-0R 91.094,16.488 r270 top
SB33 "SB_OFF" SOLDER-BRIDGE_R0603-0R 94.092,36.32 r0 top
SB34 "SB_ON" SOLDER-BRIDGE_R0603-0R 96.847,37.924 r180 top
SB35 "SB_OFF" SOLDER-BRIDGE_R0603-0R 96.933,34.403 r180 top
SB36 "SB_ON" SOLDER-BRIDGE_R0603-0R 96.925,36.32 r180 top
SB37 "SB_ON" SOLDER-BRIDGE_R0603-0R 54.651,42.326 r90 bottom
SB38 "SB_ON" SOLDER-BRIDGE_R0603-0R 51.5,38.187 r0 bottom
SB39 "SB_OFF" SOLDER-BRIDGE_R0603-0R 52.194,35.877 r270 bottom
SB40 "SB_ON" SOLDER-BRIDGE_R0603-0R 51.483,17.036 r0 bottom
SB41 "SB_OFF" SOLDER-BRIDGE_R0603-0R 51.369,40.263 r180 bottom
SB42 "SB_ON" SOLDER-BRIDGE_R0603-0R 50.722,35.872 r270 bottom
SB43 "SB_ON" SOLDER-BRIDGE_R0603-0R 49.806,29.555 r270 bottom
SB44 "SB_ON" SOLDER-BRIDGE_R0603-0R 48.092,29.484 r90 bottom
SB45 "SB_ON" SOLDER-BRIDGE_R0603-0R 47.037,58.445 r180 bottom
SB46 "SB_ON" SOLDER-BRIDGE_R0603-0R 46.56,29.501 r90 bottom
SB47 "SB_ON" SOLDER-BRIDGE_R0603-0R 23.505,54.736 r0 bottom
SB48 "SB_ON" SOLDER-BRIDGE_R0603-0R 23.48,56.614 r180 bottom
SB49 "SB_ON" SOLDER-BRIDGE_R0603-0R 24.899,31.436 r180 bottom
SB50 "SB_ON" SOLDER-BRIDGE_R0603-0R 14.494,62.212 r180 bottom
SB51 "SB_OFF" SOLDER-BRIDGE_R0603-0R 15.256,45.711 r90 bottom
SB52 "SB_OFF" SOLDER-BRIDGE_R0603-0R 11.663,62.212 r180 bottom
SB53 "SB_ON" SOLDER-BRIDGE_R0603-0R 14.352,20.438 r180 bottom
SB54 "SB_OFF" SOLDER-BRIDGE_R0603-0R 11.425,14.901 r180 bottom
SB55 "SB_OFF" SOLDER-BRIDGE_R0603-0R 11.398,13.402 r180 bottom
SB56 "SB_OFF" SOLDER-BRIDGE_R0603-0R 11.423,12.033 r180 bottom
SB57 "SB_ON" SOLDER-BRIDGE_R0603-0R 11.356,18.584 r180 bottom
SB58 "SB_ON" SOLDER-BRIDGE_R0603-0R 11.356,24.246 r180 bottom
SB59 "SB_OFF" SOLDER-BRIDGE_R0603-0R 11.339,20.463 r180 bottom
SB60 "SB_ON" SOLDER-BRIDGE_R0603-0R 11.33,25.628 r180 bottom
SB61 "SB_ON" SOLDER-BRIDGE_R0603-0R 11.297,27.102 r180 bottom
T1 "9013-SOT23" NPN_SOT23 74.33,43.321 r270 top value="NPN SOT23"
T2 "STS5PF30L" ICC_SO8_5X4_P127 47.069,38.04 r0 bottom
TP1 "Test Point" TP_SMD_1MM 7.74,57.094 r90 top
TP2 "Test Point" TP_SMD_1MM 5.004,15.005 r0 top
TP3 "Test Point" TP_SMD_1MM 10.526,58.527 r0 top
TP4 "Test Point" TP_SMD_1MM 12.436,57.665 r0 top
TP5 "Test Point" TP_SMD_1MM 10.677,56.727 r0 top
TP6 "Test Point" TP_SMD_1MM 6.899,42.581 r270 top
TP7 "Test Point" TP_SMD_1MM 7.725,55.259 r90 top
TP8 "Test Point" TP_SMD_1MM 7.725,52.759 r90 top
TP9 "Test Point" TP_SMD_1MM 20.618,46.812 r90 top
TP10 "Test Point" TP_SMD_1MM 15.106,49.158 r90 top
TP11 "Test Point" TP_SMD_1MM 23.679,54.099 r90 top
TP12 "Test Point" TP_SMD_1MM 37.765,63.139 r90 top
TP13 "Test Point" TP_SMD_1MM 50.7,59.762 r90 top
TP14 "Test Point" TP_SMD_1MM 52.761,32.106 r90 top
TP15 "Test Point" TP_SMD_1MM 55.03,28.313 r90 top
TP16 "Test Point" TP_SMD_1MM 56.977,27.09 r90 top
TP17 "Test Point" TP_SMD_1MM 57.795,38.218 r90 top
TP18 "Test Point" TP_SMD_1MM 57.637,29.579 r90 top
TP19 "Test Point" TP_SMD_1MM 59.386,28.09 r90 top
TP20 "Test Point" TP_SMD_1MM 69.757,34.132 r90 top
TP21 "Test Point" TP_SMD_1MM 91.256,25.416 r180 top
TP22 "Test Point" TP_SMD_1MM 94.339,34.427 r90 top
TP23 "Test Point" TP_SMD_1MM 96.528,26.807 r180 top
TP24 "Test Point" TP_SMD_1MM 100.262,25.505 r90 top
TP25 "Test Point" TP_SMD_1MM 103.929,30.77 r90 top
U1 "OLED_RITDISPLAY_9OL9935701000" OLED_RITDISPLAY_9OL9935701000-MB1378B-01 17.5,20.499 r0 top locked value=9OL9935701000
U2 "ESD-TRANSIL" ESD_QFN2_1P6X1_P125 21.097,6.921 r270 top value=ESDA7P60-1U1M
U3 "ESDA6V8V6-6/TR" ESD_SOT563-6L_P050 27.123,56.194 r270 top locked
U4 "ESD-TRANSIL" ESD_QFN2_1P6X1_P125 34.278,9.595 r270 top value=ESDA7P60-1U1M
U5 "NBIoT_Mod_Type1SE" MOD_BOARD_MURATA_TYPE-1SE_ES3 47.813,43.294 r0 top locked value=TYPE-1SE
U6 "LPS22HH" ICC_HLGA10_2X2_P050 54.98,16.177 r180 top
U7 "LSM303AGR" ICC_LGA12_2X2_P050 55.609,24.346 r180 top
U8 "MT25QU512ABB1EW9-0SIT" ICC_W-PDFN-8_8X6_P127 64.286,33.614 r270 top
U9 "USBLC6-2SC6" ESD_SOT23-6L 81.934,9.925 r270 top
U10 "HTS221" ICC_HLGA6_2X2_P075-1 72.196,19.737 r270 top locked
U11 "SN74LVC2T45DCUT" ICC_VSSOP8_DCU_R-PDSO-G8_2X2P30_P050 76.449,39.451 r180 top
U12 "STM32F103CBT6" ICC_LQFP48_7X7_P050 82.769,48.088 r90 top locked
U13 "USBLC6-2SC6" ESD_SOT23-6L 85.788,66.874 r0 top
U14 "SN74LVC2T45DCUT" ICC_VSSOP8_DCU_R-PDSO-G8_2X2P30_P050 83.701,55.296 r270 top
U15 "74LVC541ABQ" ICC_DHVQFN20-EPAD_SOT764-1_2P5X4P5_H0P85_P050 89.506,22.658 r90 top value=74LVC541ABQ,115
U16 "STMPS2141STR" MOS_SOT23-5L 94.887,68.176 r90 top
U17 "TS5A2066YZPR" ICC_DSBGA8_YZP_0P88X1P88_H0P50_P050 92.749,16.4 r0 top
U18 "CY7C65215-32LTXI" ICC_QFN32-EPAD_5X5_P050 96.297,21.479 r270 top locked
U19 "ST1L05BPUR" ICC_DFN6-EPAD_3X3_P095 96.273,43.529 r270 top
U20 "LD3985M33R" REG_SOT23-5L 97.703,50.217 r90 top
U21 "ESD-TRANSIL" ESD_QFN2_1P6X1_P125 101.118,69.816 r180 top value=ESDA7P60-1U1M
U22 "USBLC6-2SC6" ESD_SOT23-6L 103.455,9.265 r180 top
U23 "M24128-DFMN6TP" ICC_SO8_5X4_P127 30.029,33.401 r270 bottom
U24 "MAX9867ETJ+" ICC_TQFN32-EPAD_5X5_H0P75_P050 14.913,54.65 r180 bottom
U25 "ST1L05BPUR" ICC_DFN6-EPAD_3X3_P095 25.809,45.523 r180 bottom
U26 "ESDA6V1BC6" ESD_SOT23-6L 6.035,60.893 r270 bottom
U27 "TXS0108EPWR" ICC_TSSOP20_6P50X4P40_P065 17.553,15.079 r270 bottom locked
U28 "TXS0108EPWR" ICC_TSSOP20_6P50X4P40_P065 17.331,24.832 r270 bottom locked
U29 "TXS0108EPWR" ICC_TSSOP20_6P50X4P40_P065 17.321,33.773 r270 bottom
U30 "ST1L05BPUR" ICC_DFN6-EPAD_3X3_P095 10.866,41.643 r180 bottom
X1 "XTAL_2_PINS" CRY_NX3225GD_2P 90.555,46.432 r90 top value="NX3225GD 8MHz"
X2 "7Z26070003" CRY_NDK_NT2016SB_4P 23.43,50.363 r90 bottom value=26MHz

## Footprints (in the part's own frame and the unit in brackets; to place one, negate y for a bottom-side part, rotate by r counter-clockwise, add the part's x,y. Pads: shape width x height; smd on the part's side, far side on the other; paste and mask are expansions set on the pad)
BAT_KEYSTONE_PC-MOUNT-2479_HOLDER_AAA_X3 [mm] "MCD-01623"
  round 1.8 hole 1.1 mask+0.05: 1(23.72,-11.75) 2(23.72,0.95)
  silkscreen extent -26.85,-19 26.85,19, body extent -26.85,-19 26.85,19, height 13.5
C0402 [mm]
  rect 0.51x0.56 smd mask+0.05: 1(-0.45,0) 2(0.45,0)
  silkscreen extent 0,-0.3 0,0.3, body extent -0.5,-0.3 0.5,0.3, height 0.4
C0603 [mm]
  rect 0.64x0.89 smd mask+0.05: 1(-0.7,0) 2(0.7,0)
  silkscreen extent -1.05,-0.55 1.02,0.55, body extent -0.9,-0.5 0.9,0.5, height 1.4
C0805 [mm]
  rect 0.9x1.4 smd mask+0.05: 1(-0.85,0) 2(0.85,0)
  silkscreen extent -1.3,-0.77 1.3,0.77, body extent -1.1,-0.7 1.1,0.7, height 1.35
CON_988-JIUBABA_PHFS25-11-04-G0B115-T-1 [mm]
  rect 1.4x1.6 hole 1 mask+0.05: 1(3.81,0)
  oval 1.4x1.6 hole 1 mask+0.05: 2(1.27,0) 3(-1.27,0) 4(-3.81,0)
  silkscreen extent -5.25,-1.33 5.25,1.33, body extent -5.25,-1.33 5.25,1.33, height 8.85
CON_988-JIUBABA_PHFS25-11-06-G0B115-T-1 [mm]
  rrect50% 1.6x1.4 hole 1 mask+0.05: 1(6.35,0)
  oval 1.6x1.4 hole 1 mask+0.05: 2(3.81,0) 3(1.27,0) 4(-1.27,0) 5(-3.81,0)
  round 1.6 hole 1 mask+0.05: 6(-6.35,0)
  silkscreen extent -7.79,-1.33 7.79,1.33, body extent -7.79,-1.33 7.79,1.33, height 8.85
CON_HRS_U.FL-R-SMT-1 [mm] "MCD-01583"
  rect 1x1 smd mask+0.05: 1(0,-1.5)
  rect 1.1x2.2 smd mask+0.05: 2(-1.5,0) 3(1.5,0)
  silkscreen extent -1.12,-1.3 1.12,1.55, body extent -5.16,-2.05 5.16,1.5, height 1.25
CON_MICRO-SIMCARD_MUP_MUP-C792 [mm] "MCD-01699"
  rect 0.9x1.35 smd mask+0.05: 1(-7.405,17.105) C1(2.755,17.105) C2(0.215,17.105) C3(-2.325,17.105) C5(1.485,17.105) C6(-1.055,17.105) C7(-3.595,17.105)
  rect 1.56x2.61 smd mask+0.05: 2(-8.34,14.23) 3(-8.34,1.6) 4(8.34,1.6) 5(8.34,14.23)
  Top Layer keep-out region: -3.005,7.86 -1.605,7.86 -1.605,11.8 -3.005,11.8
  Top Layer keep-out region: -0.465,7.86 0.935,7.86 0.935,11.8 -0.465,11.8
  Top Layer keep-out region: 2.075,7.86 3.475,7.86 3.475,11.8 2.075,11.8
  Top Layer keep-out region: 4.615,0 7.705,0 7.705,17 4.615,17
  Top Layer keep-out region: 1.925,0.48 3.625,0.48 3.625,4.06 1.925,4.06
  Top Layer keep-out region: -0.615,0.48 1.085,0.48 1.085,4.06 -0.615,4.06
  Top Layer keep-out region: -3.155,0.48 -1.455,0.48 -1.455,4.06 -3.155,4.06
  silkscreen extent -7.87,0 7.88,17.17, body extent -8.37,0 8.37,17.17, height 1.5
CON_PHONE-JACK-3P5_TAIYI_PJ31060 [mm] "MCD-01695"
  round 0 hole 3.4 square unplated mask+0.05: 0(-0.4,0)
  round 0 hole 1.5 unplated mask+0.05: 0(10.5,0)
  rect 1.5x1.5 smd mask+0.05: 1(2.95,-3.65) 2(2.95,3.65) 3(5.5,-3.65) 4(9.5,3.65) 5(10.5,-3.65) 6(11.5,3.65)
  silkscreen extent -2,-3.1 12,3.1, body extent -2,-3.9 12,3.9, height 5
CON_ROHO_SMA_RFSMARA-7053 [mm] "MCD-01625"
  rect 2.5x2.5 hole 1.65 mask+0.05: 1(-2.54,2.54) 2(-2.54,-2.54) 3(2.54,-2.54) 4(2.54,2.54)
  silkscreen extent -12.8,-3.5 3.5,3.5, body extent -12.8,-3.5 20.5,3.5, height 8.9
CON_SAMTEC_SQT-110-01-F-D-RA__STMOD+ [mm] "SQT-110-01-F-D-RA (connecteur SAMTEC pour interface STMod+ femelle cot?Host) Pinning adapt?non conforme SAMTEC."
  rect 1.4x1.7 hole 0.9 mask+0.05: 1(9,1)
  oval 1.4x1.7 hole 0.9 mask+0.05: 2(7,1) 3(5,1) 4(3,1) 5(1,1) 6(-1,1) 7(-3,1) 8(-5,1) 11(9,-1) 12(7,-1) 13(5,-1) 14(3,-1) 15(1,-1) 16(-1,-1) 17(-3,-1) 18(-5,-1) 19(-7,-1) 20(-9,-1)
  oval 1.4x1.5 hole 0.9 mask+0.05: 9(-7,1) 10(-9,1)
  silkscreen extent -10.15,-8.62 10.15,0.07, body extent -10.15,-8.65 10.15,1.22, height 4
CON_SAMTEC_TSM-125-01-F-DV-A [mm] "MCD-01931"
  round 0 hole 1.73 unplated mask+0.05: 0(-29.21,0) 0(29.21,0)
  oct 1.27x3.68 smd paste+0 mask+0.05: 1(-30.48,-2.475) 2(-30.48,2.475) 3(-27.94,-2.475) 4(-27.94,2.475) 47(27.94,-2.475) 48(27.94,2.475) 49(30.48,-2.475) 50(30.48,2.475)
  rect 1.27x3.68 smd paste+0 mask+0.05: 5(-25.4,-2.475) 6(-25.4,2.475) 7(-22.86,-2.475) 8(-22.86,2.475) 9(-20.32,-2.475) 10(-20.32,2.475) 11(-17.78,-2.475) 12(-17.78,2.475) 13(-15.24,-2.475) 14(-15.24,2.475) 15(-12.7,-2.475) 16(-12.7,2.475) 17(-10.16,-2.475) 18(-10.16,2.475) 19(-7.62,-2.475) 20(-7.62,2.475) 21(-5.08,-2.475) 22(-5.08,2.475) 23(-2.54,-2.475) 24(-2.54,2.475) 25(0,-2.475) 26(0,2.475) 27(2.54,-2.475) 28(2.54,2.475) 29(5.08,-2.475) 30(5.08,2.475) 31(7.62,-2.475) 32(7.62,2.475) 33(10.16,-2.475) 34(10.16,2.475) 35(12.7,-2.475) 36(12.7,2.475) 37(15.24,-2.475) 38(15.24,2.475) 39(17.78,-2.475) 40(17.78,2.475) 41(20.32,-2.475) 42(20.32,2.475) 43(22.86,-2.475) 44(22.86,2.475) 45(25.4,-2.475) 46(25.4,2.475)
  silkscreen extent -31.75,-2.16 31.75,2.16, body extent -31.75,-3.85 31.75,3.85, height 9.65
CON_SAMTEC_TSW-102-07-G-S#1 [mm]
  rrect30% 1.4x1.85 hole 1 mask+0.05: 1(-1.27,0)
  oval 1.4x1.8 hole 1 mask+0.05: 2(1.27,0)
  silkscreen extent -2.58,-1.3 2.58,1.3, body extent -2.67,-1.3 2.58,1.3, height 8.38
CON_SAMTEC_TSW-102-07-G-S#2 [mm]
  rect 1.85x1.85 / inner round 1.85 / far side rect 1.85x1.85 hole 1 mask+0.05: 1(-1.27,0)
  round 1.85 hole 1 mask+0.05: 2(1.27,0)
  silkscreen extent -2.58,-1.3 2.58,1.3, body extent -2.67,-1.3 2.58,1.3, height 8.38
CON_SAMTEC_TSW-102-07-G-S#3 [mm]
  rect 1.6x1.6 hole 1 mask+0.05: 1(-1.27,0)
  round 1.6 hole 1 mask+0.05: 2(1.27,0)
  silkscreen extent -2.58,-1.3 2.58,1.3, body extent -2.67,-1.3 2.58,1.3, height 8.38
CON_SAMTEC_TSW-102-08-G-S [mm] "MCD-01581"
  rect 1.85x1.85 / inner round 1.85 / far side rect 1.85x1.85 hole 1 mask+0.05: 1(-1.27,0)
  round 1.85 hole 1 mask+0.05: 2(1.27,0)
  silkscreen extent -2.58,-1.3 2.58,1.3, body extent -2.67,-1.3 2.58,1.3, height 8.38
CON_TAG-C_TC2050-IDC-NL [mm]
  round 0.9 smd paste+0 mask+0.05: 1(-2.54,-0.635) 2(-1.27,-0.635) 3(0,-0.635) 4(1.27,-0.635) 5(2.54,-0.635) 6(2.54,0.635) 7(1.27,0.635) 8(0,0.635) 9(-1.27,0.635) 10(-2.54,0.635)
  round 0 hole 1.1 unplated mask+0.05: 11(-3.81,0) 12(3.81,-1.015) 13(3.81,1.015)
  Multi-Layer keep-out circle w0.01: c-3.81,0 r0.75
  Multi-Layer keep-out circle w0.01: c3.81,1.015 r0.75
  Multi-Layer keep-out circle w0.01: c3.81,-1.015 r0.75
  silkscreen extent -6.22,-3.4 6.22,3.33, body extent -6.28,-3.46 6.28,3.39, height 13
CON_USBMICROB_MOLEX_105164-0001_H2P45 [mm] "MCD-01698"
  round 0 hole 0.9 slot 2.5 at 0 deg unplated mask+0.1: 0(0.8,2.375) 0(0.8,-2.375)
  rect 1.38x0.45 smd mask+0.05: 1(4.11,-1.3) 2(4.11,-0.65) 3(4.11,0) 4(4.11,0.65) 5(4.11,1.3)
  rect 2.1x1.475 smd mask+0.05: 6(3.75,2.462) 9(3.75,-2.462)
  rect 1.9x1.375 smd mask+0.05: 7(1.45,0.937) 8(1.45,-0.937)
  oval 2.1x1.4 hole 0.6 slot 1.3 at 0 deg mask+0.05: 10(1.45,3.95) 11(1.45,-3.95)
  silkscreen extent -0.7,-3.8 4.6,3.8, body extent -0.7,-4.1 4.6,4.1, height 2.45
CPOL_TAJ-A_1206_H180 [mm]
  rect 1.45x1.6 smd mask+0.05: 1(-1.175,0) 2(1.175,0)
  silkscreen extent -2.15,-1.05 1.7,1.05, body extent -1.7,-0.9 1.7,0.9, height 1.8
CRY_NDK_NT2016SB_4P [mm] "MCD-01492"
  rect 0.6x0.8 smd mask+0.05: 1(-0.9,-0.6) 2(0.9,-0.6) 3(0.9,0.6) 4(-0.9,0.6)
  silkscreen extent -1.32,-1.12 1.05,0.85, body extent -1.05,-0.85 1.05,0.85, height 0.81
CRY_NX3225GD_2P [mm]
  rect 1.5x2.7 smd mask+0.05: 1(-0.95,0) 2(0.95,0)
  silkscreen extent -0.1,-1.3 0.1,1.3, body extent -1.65,-1.3 1.65,1.3, height 1
DIO_SOD323 [mm]
  rect 1.06x0.54 smd mask+0.05: 1(-1.07,0) 2(1.07,0)
  silkscreen extent -0.9,-0.72 0.9,0.72, body extent -1.3,-0.78 1.3,0.78, height 1.17
ESD_QFN2_1P6X1_P125 [mm]
  rect 0.55x0.8 smd mask+0.05: 1(-0.625,0) 2(0.625,0)
  silkscreen extent -1,-0.55 0.85,0.55, body extent -0.85,-0.55 0.85,0.55, height 0.61
ESD_SOT23-6L [mm]
  rect 0.6x1.2 smd mask+0.05: 1(-0.95,-1.15) 2(0,-1.15) 3(0.95,-1.15) 4(0.95,1.15) 5(0,1.15) 6(-0.95,1.15)
  silkscreen extent -1.53,-0.87 1.53,0.87, body extent -1.52,-1.5 1.52,1.5, height 1.45
ESD_SOT563-6L_P050 [mm]
  rect 0.3x0.45 smd mask+0.05: 1(-0.5,-0.675) 2(0,-0.675) 3(0.5,-0.675) 4(0.5,0.675) 5(0,0.675) 6(-0.5,0.675)
  silkscreen extent -1,-1 0.85,0.65, body extent -0.8,-0.81 1.01,0.81, height 0.6
ICC_DFN6-EPAD_3X3_P095 [mm]
  rect 0.45x0.5 smd mask+0.05: 1(-0.95,-1.3) 2(0,-1.3) 3(0.95,-1.3) 4(0.95,1.3) 5(0,1.3) 6(-0.95,1.3)
  rect 2.5x1.7 smd mask+0.05: EP(0,0)
  silkscreen extent -1.55,-1.55 1.55,1.55, body extent -1.55,-1.55 1.55,1.55, height 1
ICC_DHVQFN20-EPAD_SOT764-1_2P5X4P5_H0P85_P050 [mm] "MCD-01620"
  rect 0.3x0.8 smd mask+0.05: 1(-0.25,2.2) 10(-0.25,-2.2) 11(0.25,-2.2) 20(0.25,2.2)
  rect 0.8x0.3 smd mask+0.05: 2(-1.2,1.75) 3(-1.2,1.25) 4(-1.2,0.75) 5(-1.2,0.25) 6(-1.2,-0.25) 7(-1.2,-0.75) 8(-1.2,-1.25) 9(-1.2,-1.75) 12(1.2,-1.75) 13(1.2,-1.25) 14(1.2,-0.75) 15(1.2,-0.25) 16(1.2,0.25) 17(1.2,0.75) 18(1.2,1.25) 19(1.2,1.75)
  rect 1.2x3.2 smd mask+0.05: 21(0,0)
  silkscreen extent -1.3,-2.3 1.3,2.3, body extent -1.3,-2.3 1.3,2.3, height 1.01
ICC_DSBGA8_YZP_0P88X1P88_H0P50_P050 [mm] "MCD-01624"
  round 0.23 smd mask+0.05: A1(-0.25,0.75) A2(0.25,0.75) B1(-0.25,0.25) B2(0.25,0.25) C1(-0.25,-0.25) C2(0.25,-0.25) D1(-0.25,-0.75) D2(0.25,-0.75)
  silkscreen extent -0.63,-0.97 0.48,1.12, body extent -0.46,-0.96 0.46,0.96, height 0.63
ICC_HLGA6_2X2_P075-1 [mm] "MCD-01447"
  rect 0.35x0.4 smd mask+0.05: 1(-0.75,0.5) 2(-0.75,-0.5) 4(0.75,-0.5) 5(0.75,0.5)
  rect 0.4x0.35 smd mask+0.05: 3(0,-0.75) 6(0,0.75)
  silkscreen extent -1.17,-1.05 1.05,1.17, body extent -1.05,-1.05 1.05,1.05, height 1.01
ICC_HLGA10_2X2_P050 [mm] "MCD-01449"
  rect 0.325x0.3 smd mask+0.05: 1(-0.763,0.25) 2(-0.763,-0.25) 6(0.763,-0.25) 7(0.763,0.25)
  rect 0.3x0.325 smd mask+0.05: 3(-0.5,-0.762) 4(0,-0.762) 5(0.5,-0.762) 8(0.5,0.763) 9(0,0.763) 10(-0.5,0.763)
  silkscreen extent -1.17,-1.05 1.05,1.17, body extent -1.05,-1.05 1.05,1.05, height 0.8
ICC_LGA12_2X2_P050 [mm] "MCD-00709"
  rect 0.325x0.3 smd mask+0.05: 1(-0.763,0.75) 2(-0.763,0.25) 3(-0.763,-0.25) 4(-0.763,-0.75) 7(0.763,-0.75) 8(0.763,-0.25) 9(0.763,0.25) 10(0.763,0.75)
  rect 0.3x0.325 smd mask+0.05: 5(-0.25,-0.762) 6(0.25,-0.762) 11(0.25,0.763) 12(-0.25,0.763)
  silkscreen extent -1.2,-1.05 1.05,1.2, body extent -1.05,-1.05 1.05,1.05, height 1.01
ICC_LQFP48_7X7_P050 [mm]
  rect 0.3x1.2 smd mask+0.05: 1(-2.75,-4.25) 2(-2.25,-4.25) 3(-1.75,-4.25) 4(-1.25,-4.25) 5(-0.75,-4.25) 6(-0.25,-4.25) 7(0.25,-4.25) 8(0.75,-4.25) 9(1.25,-4.25) 10(1.75,-4.25) 11(2.25,-4.25) 12(2.75,-4.25) 25(2.75,4.25) 26(2.25,4.25) 27(1.75,4.25) 28(1.25,4.25) 29(0.75,4.25) 30(0.25,4.25) 31(-0.25,4.25) 32(-0.75,4.25) 33(-1.25,4.25) 34(-1.75,4.25) 35(-2.25,4.25) 36(-2.75,4.25)
  rect 1.2x0.3 smd mask+0.05: 13(4.25,-2.75) 14(4.25,-2.25) 15(4.25,-1.75) 16(4.25,-1.25) 17(4.25,-0.75) 18(4.25,-0.25) 19(4.25,0.25) 20(4.25,0.75) 21(4.25,1.25) 22(4.25,1.75) 23(4.25,2.25) 24(4.25,2.75) 37(-4.25,2.75) 38(-4.25,2.25) 39(-4.25,1.75) 40(-4.25,1.25) 41(-4.25,0.75) 42(-4.25,0.25) 43(-4.25,-0.25) 44(-4.25,-0.75) 45(-4.25,-1.25) 46(-4.25,-1.75) 47(-4.25,-2.25) 48(-4.25,-2.75)
  silkscreen extent -3.52,-3.52 3.52,3.52, body extent -4.5,-4.5 4.5,4.5, height 1.6
ICC_QFN32-EPAD_5X5_P050 [mm]
  oval 0.3x0.75 smd mask+0.05: 1(-1.75,-2.425) 2(-1.25,-2.425) 3(-0.75,-2.425) 4(-0.25,-2.425) 5(0.25,-2.425) 6(0.75,-2.425) 7(1.25,-2.425) 8(1.75,-2.425) 17(1.75,2.425) 18(1.25,2.425) 19(0.75,2.425) 20(0.25,2.425) 21(-0.25,2.425) 22(-0.75,2.425) 23(-1.25,2.425) 24(-1.75,2.425)
  oval 0.75x0.3 smd mask+0.05: 9(2.425,-1.75) 10(2.425,-1.25) 11(2.425,-0.75) 12(2.425,-0.25) 13(2.425,0.25) 14(2.425,0.75) 15(2.425,1.25) 16(2.425,1.75) 25(-2.425,1.75) 26(-2.425,1.25) 27(-2.425,0.75) 28(-2.425,0.25) 29(-2.425,-0.25) 30(-2.425,-0.75) 31(-2.425,-1.25) 32(-2.425,-1.75)
  rect 3.7x3.7 smd mask+0.05: 33(0,0)
  silkscreen extent -2.63,-2.63 2.63,2.63, body extent -2.55,-2.55 2.55,2.55, height 1
ICC_SO8_5X4_P127 [mm]
  rect 0.7x1.75 smd mask+0.05: 1(-1.905,-2.375) 2(-0.635,-2.375) 3(0.635,-2.375) 4(1.905,-2.375) 5(1.905,2.375) 6(0.635,2.375) 7(-0.635,2.375) 8(-1.905,2.375)
  silkscreen extent -2.73,-3.25 2.58,2, body extent -2.57,-3 2.57,3, height 1.75
ICC_TQFN32-EPAD_5X5_H0P75_P050 [mm] "MCD-01621"
  oval 0.3x0.75 smd mask+0.05: 1(-1.75,-2.425) 2(-1.25,-2.425) 3(-0.75,-2.425) 4(-0.25,-2.425) 5(0.25,-2.425) 6(0.75,-2.425) 7(1.25,-2.425) 8(1.75,-2.425) 17(1.75,2.425) 18(1.25,2.425) 19(0.75,2.425) 20(0.25,2.425) 21(-0.25,2.425) 22(-0.75,2.425) 23(-1.25,2.425) 24(-1.75,2.425)
  oval 0.75x0.3 smd mask+0.05: 9(2.425,-1.75) 10(2.425,-1.25) 11(2.425,-0.75) 12(2.425,-0.25) 13(2.425,0.25) 14(2.425,0.75) 15(2.425,1.25) 16(2.425,1.75) 25(-2.425,1.75) 26(-2.425,1.25) 27(-2.425,0.75) 28(-2.425,0.25) 29(-2.425,-0.25) 30(-2.425,-0.75) 31(-2.425,-1.25) 32(-2.425,-1.75)
  rect 3.7x3.7 smd mask+0.05: 33(0,0)
  silkscreen extent -2.63,-2.63 2.63,2.63, body extent -2.55,-2.55 2.55,2.55, height 0.8
ICC_TSSOP20_6P50X4P40_P065 [mm]
  rect 0.4x1.6 smd mask+0.05: 1(-2.925,-2.8) 2(-2.275,-2.8) 3(-1.625,-2.8) 4(-0.975,-2.8) 5(-0.325,-2.8) 6(0.325,-2.8) 7(0.975,-2.8) 8(1.625,-2.8) 9(2.275,-2.8) 10(2.925,-2.8) 11(2.925,2.8) 12(2.275,2.8) 13(1.625,2.8) 14(0.975,2.8) 15(0.325,2.8) 16(-0.325,2.8) 17(-0.975,2.8) 18(-1.625,2.8) 19(-2.275,2.8) 20(-2.925,2.8)
  silkscreen extent -3.3,-2.25 3.3,2.25, body extent -3.3,-3.3 3.3,3.3, height 1.21
ICC_VSSOP8_DCU_R-PDSO-G8_2X2P30_P050 [mm]
  rect 0.3x0.8 smd mask+0.05: 1(-0.75,-1.55) 2(-0.25,-1.55) 3(0.25,-1.55) 4(0.75,-1.55) 5(0.75,1.55) 6(0.25,1.55) 7(-0.25,1.55) 8(-0.75,1.55)
  silkscreen extent -1.05,-1.2 1.05,1.2, body extent -1.05,-1.62 1.05,1.62, height 0.9
ICC_W-PDFN-8_8X6_P127 [mm]
  rect 1.35x0.8 smd mask+0.05: 1(-3.575,1.905) 2(-3.575,0.635) 3(-3.575,-0.635) 4(-3.575,-1.905) 5(3.575,-1.905) 6(3.575,-0.635) 7(3.575,0.635) 8(3.575,1.905)
  rect 4x5 smd mask+0.05: 9(0,0)
  silkscreen extent -4.47,-3 4,3, body extent -4,-3 4,3, height 0.81
L0603 [mm]
  rect 0.8x0.95 smd mask+0.05: 1(-0.8,0) 2(0.8,0)
  silkscreen extent -1.33,-0.6 1.33,0.6, body extent -0.87,-0.47 0.87,0.47, height 0.95
L0603_H0P8 [mm]
  rect 0.8x0.95 smd mask+0.05: 1(-0.8,0) 2(0.8,0)
  silkscreen extent -1.33,-0.6 1.33,0.6, body extent -0.87,-0.47 0.87,0.47, height 0.9
Label [mm]
  silkscreen extent 0,0 25,9
LED_0603_GREEN_H0P8 [mm]
  rect 0.8x0.8 smd mask+0.05: 1(-0.75,0) 2(0.75,0)
  silkscreen extent -0.25,-0.4 1.25,0.4, body extent -0.8,-0.4 0.8,0.4, height 0.8
LED_0603_OSRAM_LB-Q39G-L2OO-35-1_BLUE_1A2K_H0P4 [mm]
  rect 0.8x0.8 smd mask+0.05: 1(-0.75,0) 2(0.75,0)
  silkscreen extent -0.85,-0.53 1.28,0.53, body extent -0.85,-0.45 0.85,0.45, height 0.6
LED_0603_RED [mm]
  rect 0.8x0.8 smd mask+0.05: 1(-0.75,0) 2(0.75,0)
  silkscreen extent -0.25,-0.4 1.25,0.4, body extent -0.8,-0.4 0.8,0.4, height 0.6
LED_0603_RED_H0P4 [mm]
  rect 0.8x0.8 smd mask+0.05: 1(-0.75,0) 2(0.75,0)
  silkscreen extent -0.25,-0.4 1.25,0.4, body extent -0.8,-0.4 0.79,0.4, height 0.4
LED_BI-GR_HSMF-A201-A00J1 [mm]
  rect 1.1x1.5 smd mask+0.05: 1(-0.75,-1.5) 2(-0.75,1.5) 3(0.75,1.5) 4(0.75,-1.5)
  silkscreen extent -1.65,-1.85 1.65,1.85, body extent -1.5,-1.85 1.5,1.85, height 2.1
MARK [mm]
  round 1 smd mask+0.5: 1(0,0)
  round 1 smd far side mask+0.5: 2(0,0)
  Top Layer pour cut-out: -1.5,0 -1.386,-0.574 -1.061,-1.061 -0.574,-1.386 0,-1.5 0,-1.5 0.574,-1.386 1.061,-1.061 1.386,-0.574 1.5,0 1.5,0 1.386,0.574 1.061,1.061 0.574,1.386 0,1.5 0,1.5 -0.574,1.386 -1.061,1.061 -1.386,0.574 -1.5,0
  Bottom Layer pour cut-out: -1.5,0 -1.386,-0.574 -1.061,-1.061 -0.574,-1.386 0,-1.5 0,-1.5 0.574,-1.386 1.061,-1.061 1.386,-0.574 1.5,0 1.5,0 1.386,0.574 1.061,1.061 0.574,1.386 0,1.5 0,1.5 -0.574,1.386 -1.061,1.061 -1.386,0.574 -1.5,0
MOD_BOARD_MURATA_TYPE-1SE_ES3 [mm] "MCD-01700-ES3"
  rect 0.9x0.4 smd mask+0.05: 1(7.2,-7.8) 2(7.2,-7.2) 3(7.2,-6.6) 4(7.2,-6) 5(7.2,-5.4) 6(7.2,-4.8) 7(7.2,-4.2) 8(7.2,-3.6) 9(7.2,-3) 10(7.2,-2.4) 11(7.2,-1.8) 12(7.2,-1.2) 13(7.2,-0.6) 14(7.2,0) 15(7.2,0.6) 16(7.2,1.2) 17(7.2,1.8) 18(7.2,2.4) 19(7.2,3) 20(7.2,3.6) 21(7.2,4.2) 22(7.2,4.8) 23(7.2,5.4) 24(7.2,6) 25(7.2,6.6) 26(7.2,7.2) 27(7.2,7.8) 52(-7.2,7.8) 53(-7.2,7.2) 54(-7.2,6.6) 55(-7.2,6) 56(-7.2,5.4) 57(-7.2,4.8) 58(-7.2,4.2) 59(-7.2,3.6) 60(-7.2,3) 61(-7.2,2.4) 62(-7.2,1.8) 63(-7.2,1.2) 64(-7.2,0.6) 65(-7.2,0) 66(-7.2,-0.6) 67(-7.2,-1.2) 68(-7.2,-1.8) 69(-7.2,-2.4) 70(-7.2,-3) 71(-7.2,-3.6) 72(-7.2,-4.2) 73(-7.2,-4.8) 74(-7.2,-5.4) 75(-7.2,-6) 76(-7.2,-6.6) 77(-7.2,-7.2) 78(-7.2,-7.8)
  rect 0.9x0.75 smd mask+0.05: 28(7.2,8.575) 51(-7.2,8.575) 79(-7.2,-8.575) 102(7.2,-8.575)
  rect 0.4x0.9 smd mask+0.05: 29(6.3,8.5) 30(5.7,8.5) 31(5.1,8.5) 32(4.5,8.5) 33(3.9,8.5) 34(3.3,8.5) 35(2.7,8.5) 36(2.1,8.5) 37(1.5,8.5) 38(0.9,8.5) 39(0.3,8.5) 40(-0.3,8.5) 41(-0.9,8.5) 42(-1.5,8.5) 43(-2.1,8.5) 44(-2.7,8.5) 45(-3.3,8.5) 46(-3.9,8.5) 47(-4.5,8.5) 48(-5.1,8.5) 49(-5.7,8.5) 50(-6.3,8.5) 80(-6.3,-8.5) 81(-5.7,-8.5) 82(-5.1,-8.5) 83(-4.5,-8.5) 84(-3.9,-8.5) 85(-3.3,-8.5) 86(-2.7,-8.5) 87(-2.1,-8.5) 88(-1.5,-8.5) 89(-0.9,-8.5) 90(-0.3,-8.5) 91(0.3,-8.5) 92(0.9,-8.5) 93(1.5,-8.5) 94(2.1,-8.5) 95(2.7,-8.5) 96(3.3,-8.5) 97(3.9,-8.5) 98(4.5,-8.5) 99(5.1,-8.5) 100(5.7,-8.5) 101(6.3,-8.5)
  rect 1.2x1.2 smd mask+0.05: 103(2.4,-4) 104(2.4,-2.4) 105(2.4,-0.8) 106(2.4,0.8) 107(2.4,2.4) 108(2.4,4) 109(0.8,4) 110(-0.8,4) 111(-2.4,4) 112(-2.4,2.4) 113(-2.4,0.8) 114(-2.4,-0.8) 115(-2.4,-2.4) 116(-2.4,-4) 117(-0.8,-4) 118(0.8,-4) 119(0.8,-2.4) 120(0.8,-0.8) 121(0.8,0.8) 122(0.8,2.4) 123(-0.8,2.4) 124(-0.8,0.8) 125(-0.8,-0.8) 126(-0.8,-2.4)
  silkscreen extent -8.7,-10 8.7,10, body extent -8.7,-10 8.7,10, height 1.21
MOS_SOT23 [mm]
  rect 1x1.4 smd mask+0.05: 1(-0.95,-1.1) 2(0.95,-1.1) 3(0,1.1)
  silkscreen extent -1.63,-0.82 1.63,0.82, body extent -1.56,-1.25 1.56,1.25, height 1.1
MOS_SOT23-5L [mm]
  rect 0.6x1.3 smd mask+0.05: 1(-0.95,-1.1) 2(0,-1.1) 3(0.95,-1.1) 4(0.95,1.1) 5(-0.95,1.1)
  silkscreen extent -1.6,-0.95 1.6,0.97, body extent -1.52,-1.25 1.52,1.25, height 1.45
NPN_SOT23 [mm]
  rect 1x1.4 smd mask+0.05: 1(-0.95,-1.1) 2(0.95,-1.1) 3(0,1.1)
  silkscreen extent -1.63,-0.82 1.63,0.82, body extent -1.56,-1.25 1.56,1.25, height 1.1
OLED_RITDISPLAY_9OL9935701000-MB1378B-01 [mm] "OLED, 20-Leads, Body 24.94x7.50x22.80mm, Pitch 0.30mm - MB1378B-01"
  rect 0.45x3 smd paste-2 mask+0.051: 1(0.45,4.5) 2(1.15,4.5) 3(1.85,4.5) 4(2.55,4.5) 5(3.25,4.5) 6(3.95,4.5) 7(4.65,4.5) 8(5.35,4.5) 9(6.05,4.5) 10(6.75,4.5) 11(7.45,4.5) 12(8.15,4.5) 13(8.85,4.5) 14(9.55,4.5) 15(10.25,4.5) 16(10.95,4.5) 17(11.65,4.5) 18(12.35,4.5) 19(13.05,4.5) 20(13.75,4.5)
  round 0.5 hole 0.8 unplated: H1(0,0) H1(14.2,0)
  Top Layer keep-out region: -0.984,1.05 1.05,1.05 1.05,-0.903 2.016,-0.903 2.016,-1.75 12.216,-1.75 12.216,-0.903 13.2,-0.903 13.2,1.05 15.216,1.05 15.216,4.597 15.216,4.697 15.14,4.88 14.999,5.021 14.815,5.097 14.716,5.097 14.275,5.097 14.275,2.35 -0.075,2.35 -0.075,5.097 -0.483,5.097 -0.582,5.098 -0.767,5.022 -0.908,4.881 -0.984,4.697 -0.984,4.597
  Keep-Out Layer circle w0.4: c14.2,0 r0.7
  Keep-Out Layer circle w0.4: c0,0 r0.7
  silkscreen extent -5.39,-1.54 19.56,17.61, body extent -5.39,-1.54 26.1,24.35, height 4.2
PTH_M1261-3005-N_3P5X6_M3_H14 [mm]
  round 6 hole 3.5 mask+0.05: 1(0,0)
  silkscreen extent -3.25,-3.25 3.25,3.25, body extent -2.5,-2.5 2.5,2.5, height 14
R0402 [mm]
  rect 0.51x0.7 smd mask+0.05: 1(-0.45,0) 2(0.45,0)
  silkscreen extent 0,-0.3 0,0.3, body extent -0.52,-0.3 0.52,0.3, height 0.4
